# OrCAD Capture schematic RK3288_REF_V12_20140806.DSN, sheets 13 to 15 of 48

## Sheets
13 21.Power-RT5C620_1CELL: size A2; title: Power-RT5C620_1CELL; note: RK808-System Power
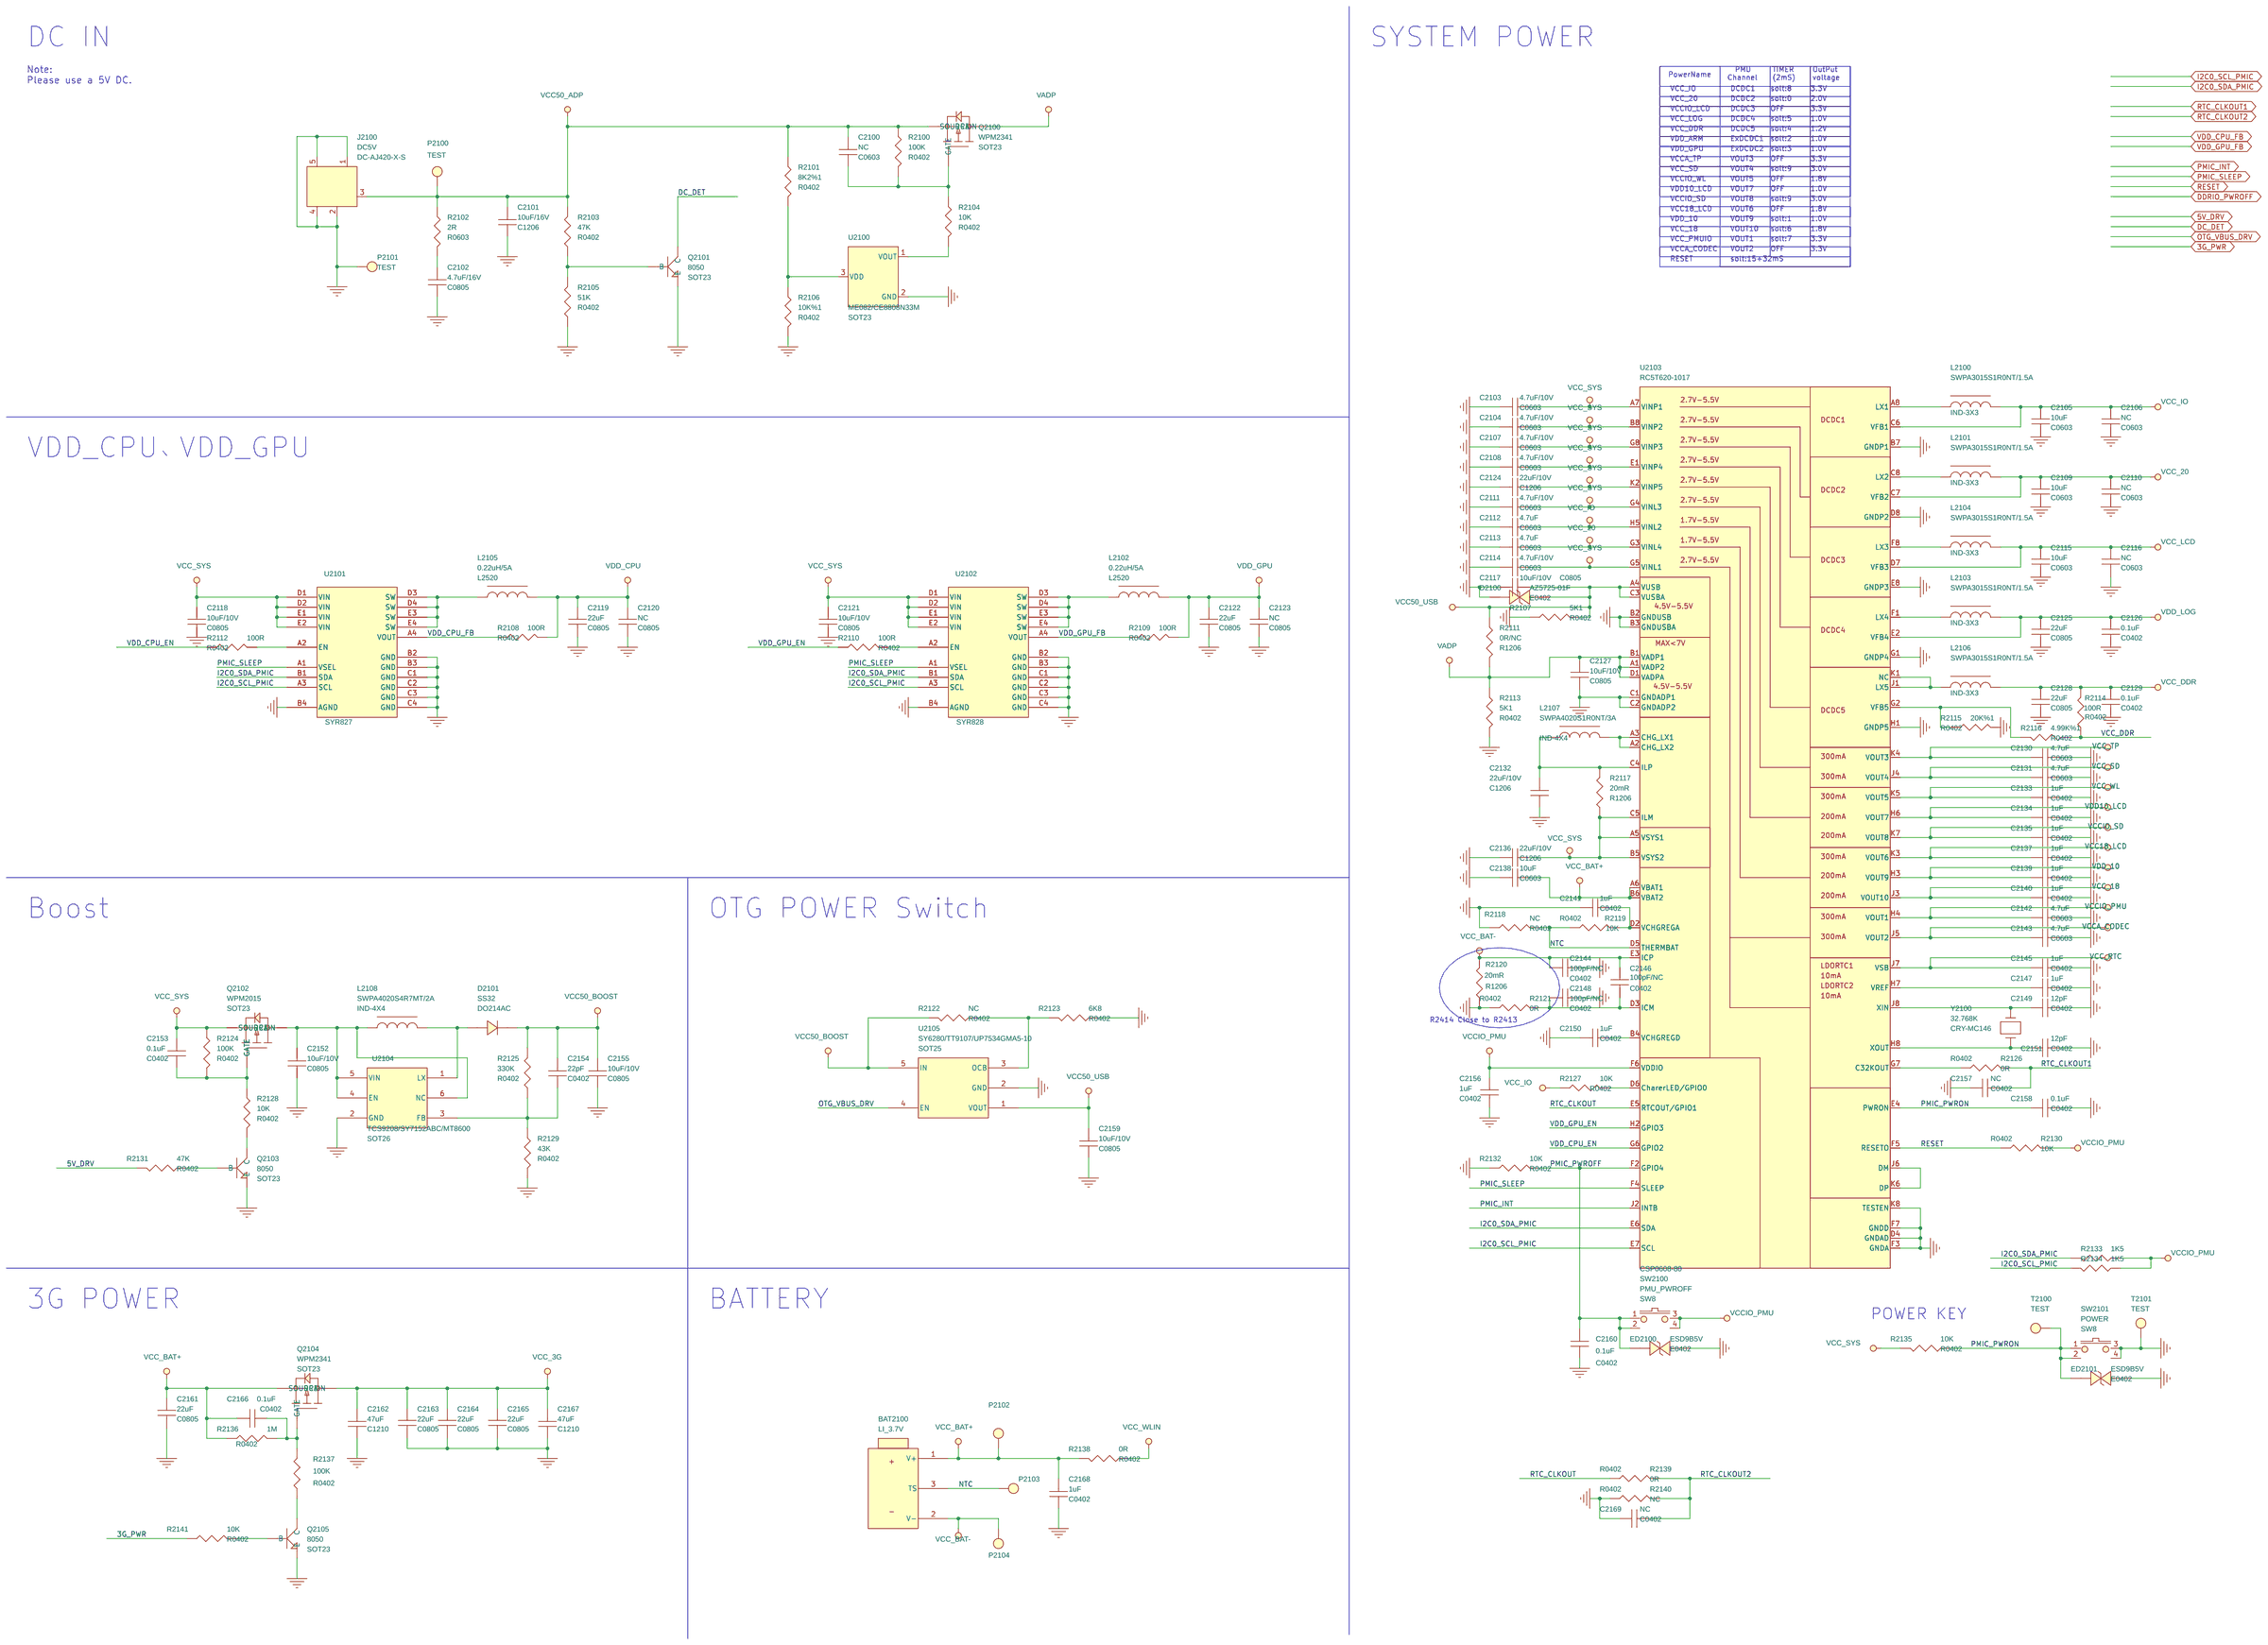
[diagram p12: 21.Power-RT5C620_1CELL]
14 22.Power-ACT8846_2CELL (option): size A2; title: Power-ACT8846_2CELL (option); note: Power Tree
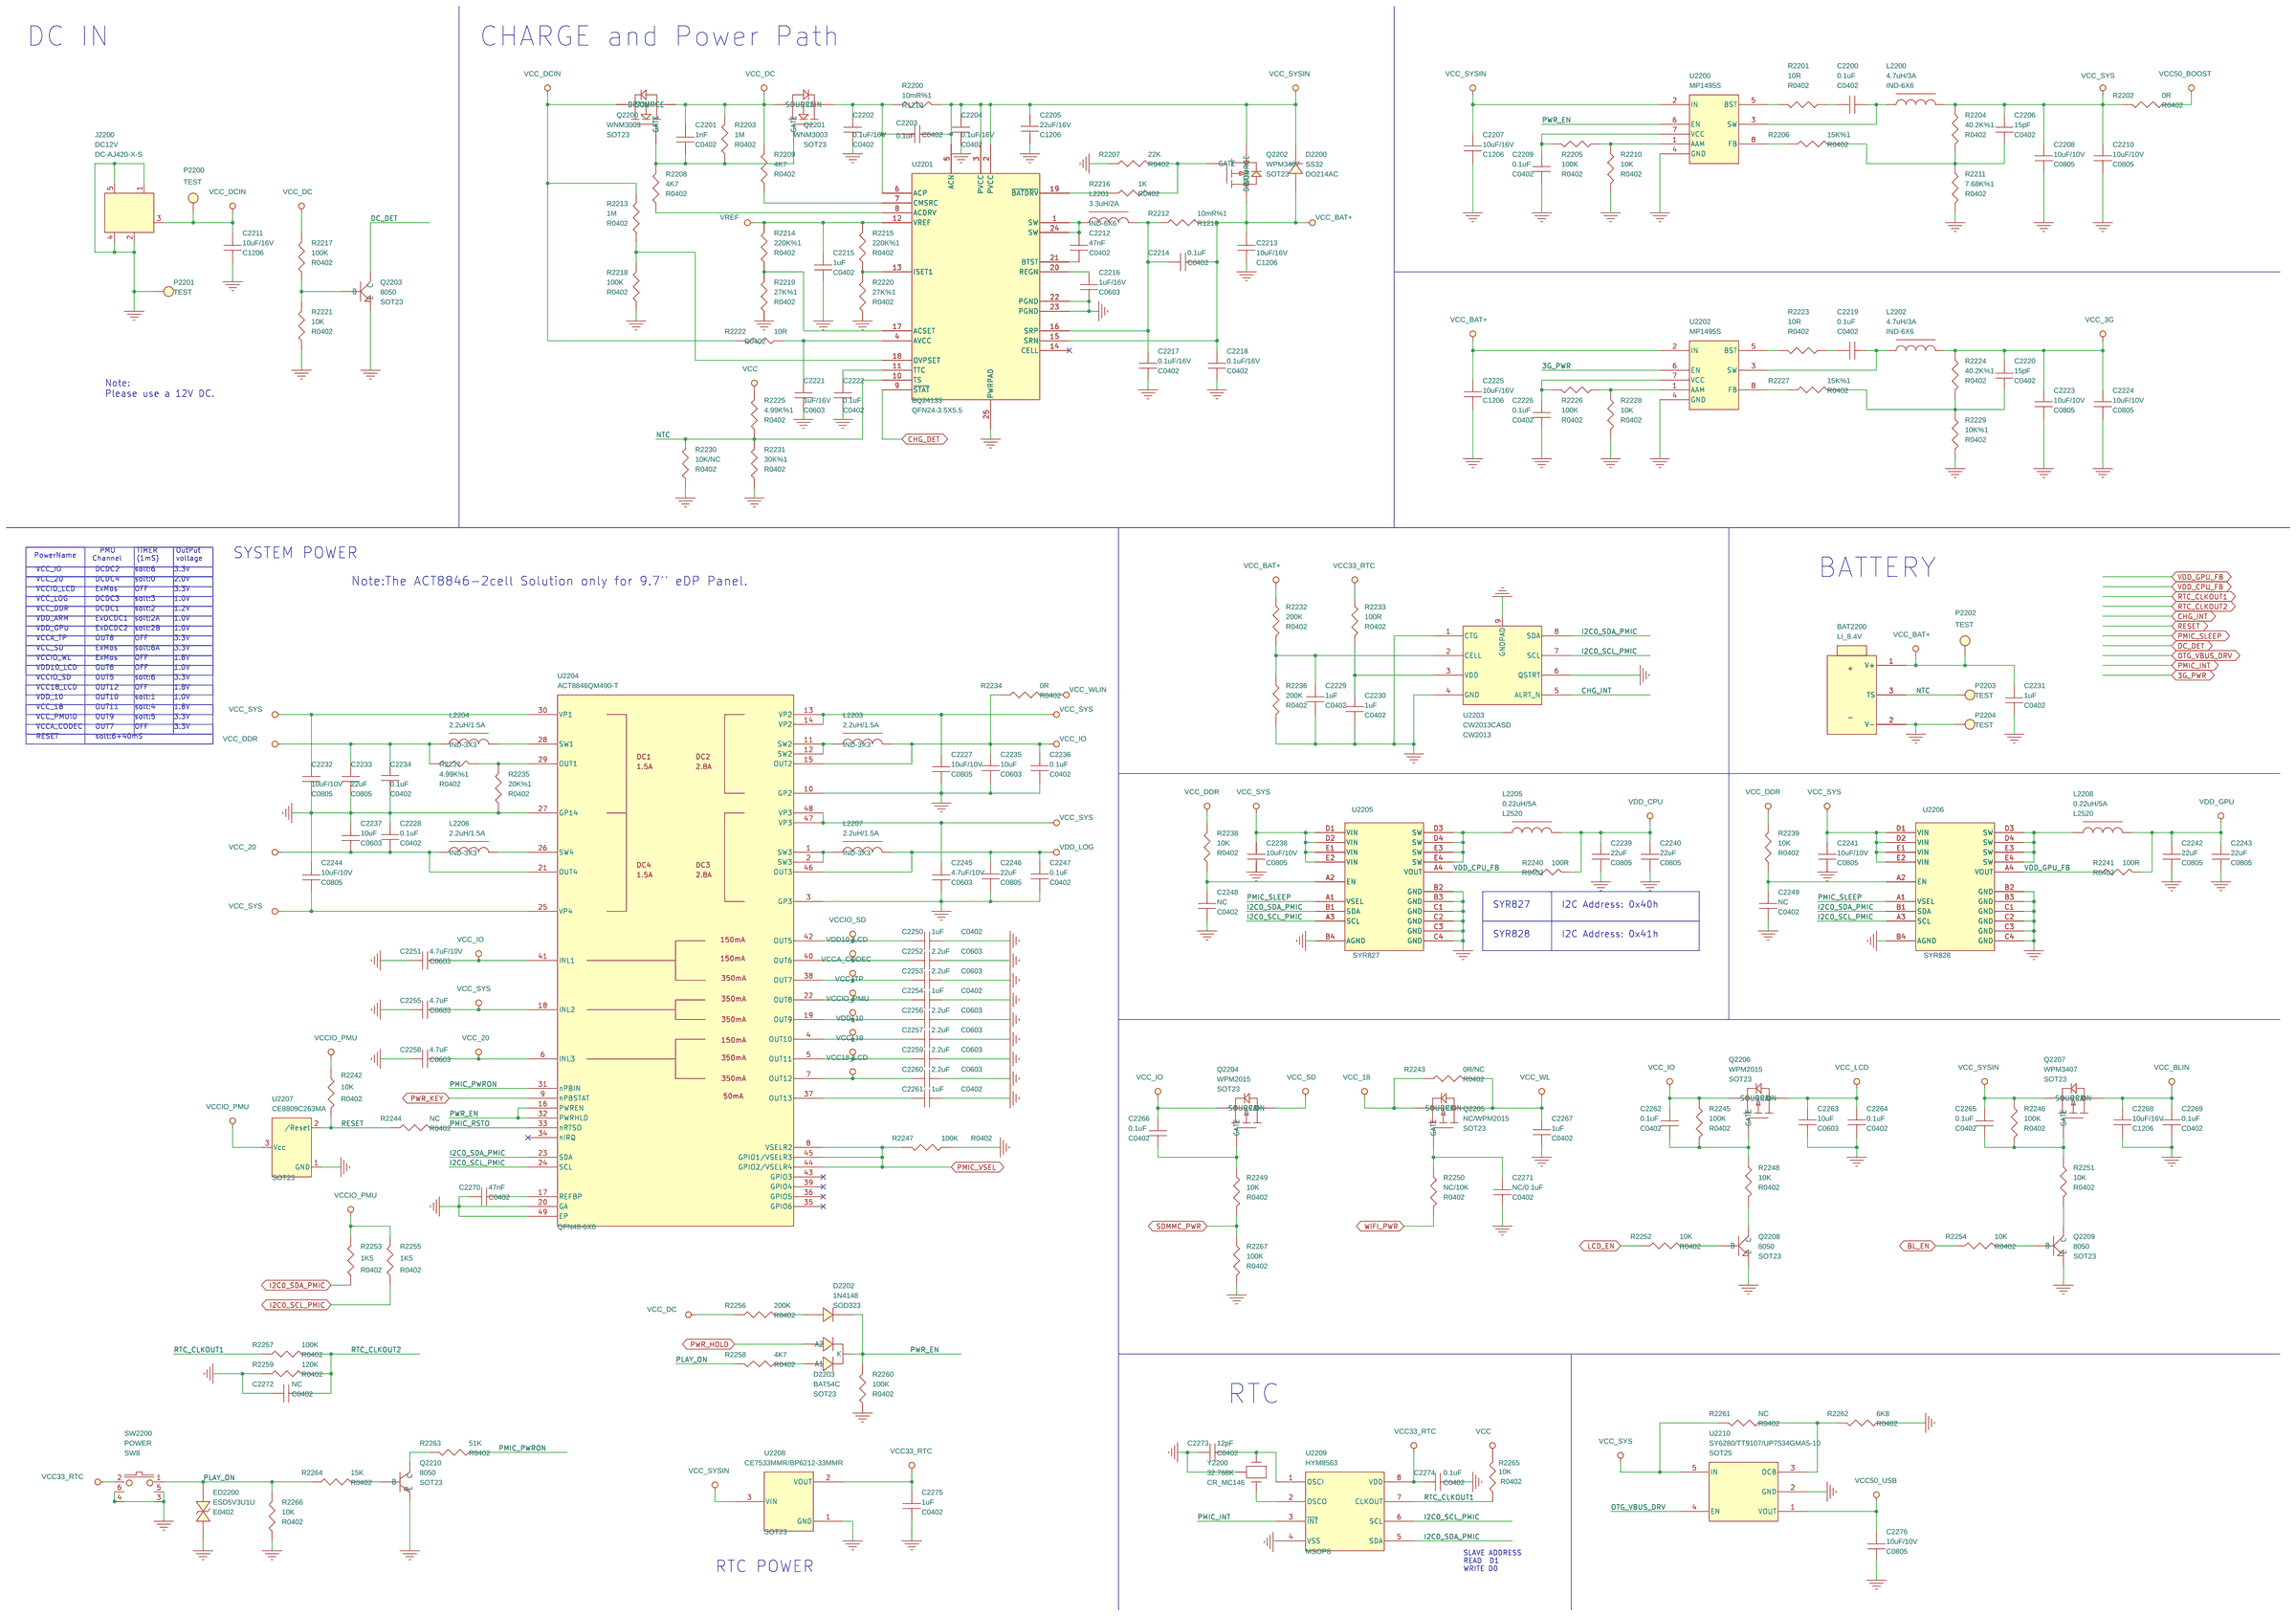
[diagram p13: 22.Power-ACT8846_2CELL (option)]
15 30.RAM-DDR3 4x16bit: size Custom; title: RAM-DDR3 4x16bit; note: RAM-DDR3 4x16bit
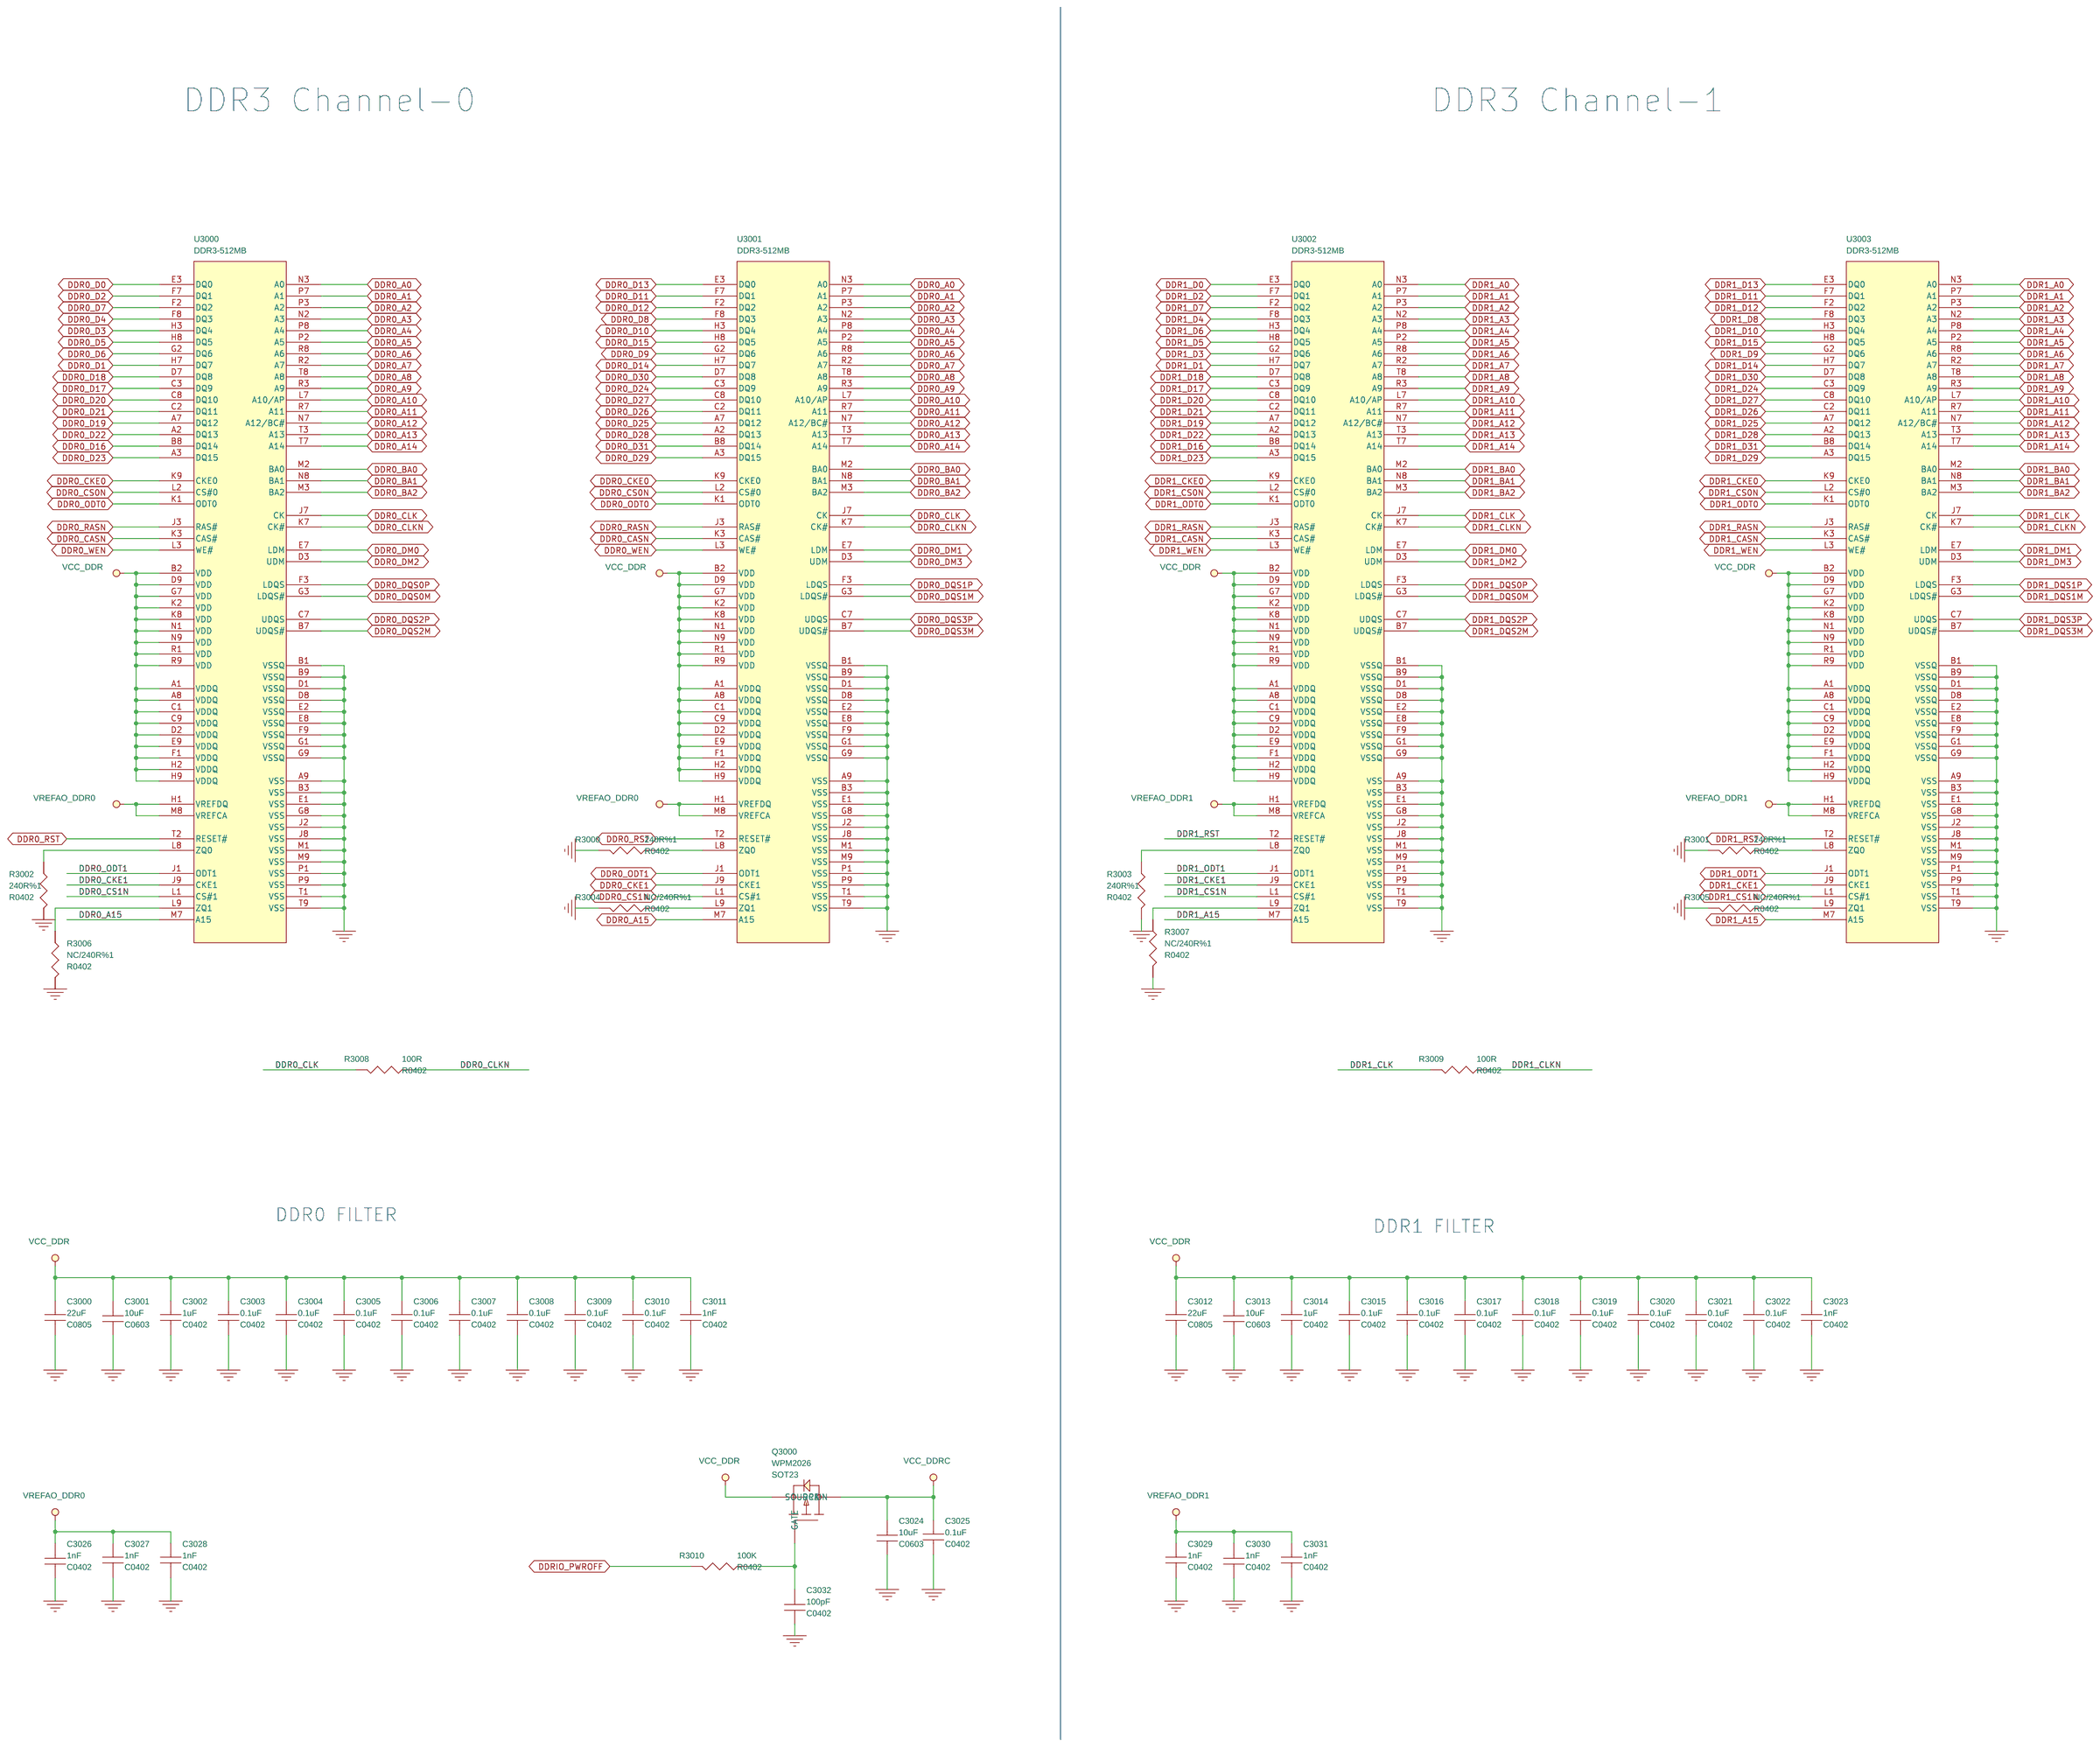
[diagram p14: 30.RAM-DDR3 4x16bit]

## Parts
sheet 21.Power-RT5C620_1CELL
BAT2100  LI_3.7V  [BAT-3]
C2100  NC  [C0603]
C2101  10uF/16V  [C1206]
C2102  4.7uF/16V  [C0805]
C2103  4.7uF/10V  [C0603]
C2104  4.7uF/10V  [C0603]
C2105  10uF  [C0603]
C2106  NC  [C0603]
C2107  4.7uF/10V  [C0603]
C2108  4.7uF/10V  [C0603]
C2109  10uF  [C0603]
C2110  NC  [C0603]
C2111  4.7uF/10V  [C0603]
C2112  4.7uF  [C0603]
C2113  4.7uF  [C0603]
C2114  4.7uF/10V  [C0603]
C2115  10uF  [C0603]
C2116  NC  [C0603]
C2117  10uF/10V  [C0805]
C2118  10uF/10V  [C0805]
C2119  22uF  [C0805]
C2120  NC  [C0805]
C2121  10uF/10V  [C0805]
C2122  22uF  [C0805]
C2123  NC  [C0805]
C2124  22uF/10V  [C1206]
C2125  22uF  [C0805]
C2126  0.1uF  [C0402]
C2127  10uF/10V  [C0805]
C2128  22uF  [C0805]
C2129  0.1uF  [C0402]
C2130  4.7uF  [C0603]
C2131  4.7uF  [C0603]
C2132  22uF/10V  [C1206]
C2133  1uF  [C0402]
C2134  1uF  [C0402]
C2135  1uF  [C0402]
C2136  22uF/10V  [C1206]
C2137  1uF  [C0402]
C2138  10uF  [C0603]
C2139  1uF  [C0402]
C2140  1uF  [C0402]
C2141  1uF  [C0402]
C2142  4.7uF  [C0603]
C2143  4.7uF  [C0603]
C2144  100pF/NC  [C0402]
C2145  1uF  [C0402]
C2146  100pF/NC  [C0402]
C2147  1uF  [C0402]
C2148  100pF/NC  [C0402]
C2149  12pF  [C0402]
C2150  1uF  [C0402]
C2151  12pF  [C0402]
C2152  10uF/10V  [C0805]
C2153  0.1uF  [C0402]
C2154  22pF  [C0402]
C2155  10uF/10V  [C0805]
C2156  1uF  [C0402]
C2157  NC  [C0402]
C2158  0.1uF  [C0402]
C2159  10uF/10V  [C0805]
C2160  0.1uF  [C0402]
C2161  22uF  [C0805]
C2162  47uF  [C1210]
C2163  22uF  [C0805]
C2164  22uF  [C0805]
C2165  22uF  [C0805]
C2166  0.1uF  [C0402]
C2167  47uF  [C1210]
C2168  1uF  [C0402]
C2169  NC  [C0402]
D2100  AZ5725-01F  [E0402]
D2101  SS32  [DO214AC]
ED2100  ESD9B5V  [E0402]
ED2101  ESD9B5V  [E0402]
J2100  DC5V  [DC-AJ420-X-S]
L2100  SWPA3015S1R0NT/1.5A  [IND-3X3]
L2101  SWPA3015S1R0NT/1.5A  [IND-3X3]
L2102  0.22uH/5A  [L2520]
L2103  SWPA3015S1R0NT/1.5A  [IND-3X3]
L2104  SWPA3015S1R0NT/1.5A  [IND-3X3]
L2105  0.22uH/5A  [L2520]
L2106  SWPA3015S1R0NT/1.5A  [IND-3X3]
L2107  SWPA4020S1R0NT/3A  [IND-4X4]
L2108  SWPA4020S4R7MT/2A  [IND-4X4]
P2100  TEST  [T-0.7]
P2101  TEST  [T-0.7]
P2102  TEST  [T-0.7]
P2103  TEST  [T-0.7]
P2104  TEST  [T-0.7]
Q2100  WPM2341  [SOT23]
Q2101  8050  [SOT23]
Q2102  WPM2015  [SOT23]
Q2103  8050  [SOT23]
Q2104  WPM2341  [SOT23]
Q2105  8050  [SOT23]
R2100  100K  [R0402]
R2101  8K2%1  [R0402]
R2102  2R  [R0603]
R2103  47K  [R0402]
R2104  10K  [R0402]
R2105  51K  [R0402]
R2106  10K%1  [R0402]
R2107  5K1  [R0402]
R2108  100R  [R0402]
R2109  100R  [R0402]
R2110  100R  [R0402]
R2111  0R/NC  [R1206]
R2112  100R  [R0402]
R2113  5K1  [R0402]
R2114  100R  [R0402]
R2115  20K%1  [R0402]
R2116  4.99K%1  [R0402]
R2117  20mR  [R1206]
R2118  NC  [R0402]
R2119  10K  [R0402]
R2120  20mR  [R1206]
R2121  0R  [R0402]
R2122  NC  [R0402]
R2123  6K8  [R0402]
R2124  100K  [R0402]
R2125  330K  [R0402]
R2126  0R  [R0402]
R2127  10K  [R0402]
R2128  10K  [R0402]
R2129  43K  [R0402]
R2130  10K  [R0402]
R2131  47K  [R0402]
R2132  10K  [R0402]
R2133  1K5  [R0402]
R2134  1K5  [R0402]
R2135  10K  [R0402]
R2136  1M  [R0402]
R2137  100K  [R0402]
R2138  0R  [R0402]
R2139  0R  [R0402]
R2140  NC  [R0402]
R2141  10K  [R0402]
SW2100  PMU_PWROFF  [SW8]
SW2101  POWER  [SW8]
T2100  TEST  [T-0.7]
T2101  TEST  [T-0.7]
U2100  ME082/CE8808N33M  [SOT23]
U2101  SYR827  [WLCSP-20]
U2102  SYR828  [WLCSP-20]
U2103  RC5T620-1017  [CSP0608-80]
U2104  TCS9208/SY7152ABC/MT8600  [SOT26]
U2105  SY6280/TT9107/UP7534GMA5-10  [SOT25]
Y2100  32.768K  [CRY-MC146]
sheet 22.Power-ACT8846_2CELL (option)
BAT2200  LI_8.4V  [BAT-3]
C2200  0.1uF  [C0402]
C2201  1nF  [C0402]
C2202  0.1uF/16V  [C0402]
C2203  0.1uF  [C0402]
C2204  0.1uF/16V  [C0402]
C2205  22uF/16V  [C1206]
C2206  15pF  [C0402]
C2207  10uF/16V  [C1206]
C2208  10uF/10V  [C0805]
C2209  0.1uF  [C0402]
C2210  10uF/10V  [C0805]
C2211  10uF/16V  [C1206]
C2212  47nF  [C0402]
C2213  10uF/16V  [C1206]
C2214  0.1uF  [C0402]
C2215  1uF  [C0402]
C2216  1uF/16V  [C0603]
C2217  0.1uF/16V  [C0402]
C2218  0.1uF/16V  [C0402]
C2219  0.1uF  [C0402]
C2220  15pF  [C0402]
C2221  1uF/16V  [C0603]
C2222  0.1uF  [C0402]
C2223  10uF/10V  [C0805]
C2224  10uF/10V  [C0805]
C2225  10uF/16V  [C1206]
C2226  0.1uF  [C0402]
C2227  10uF/10V  [C0805]
C2228  0.1uF  [C0402]
C2229  1uF  [C0402]
C2230  1uF  [C0402]
C2231  1uF  [C0402]
C2232  10uF/10V  [C0805]
C2233  22uF  [C0805]
C2234  0.1uF  [C0402]
C2235  10uF  [C0603]
C2236  0.1uF  [C0402]
C2237  10uF  [C0603]
C2238  10uF/10V  [C0805]
C2239  22uF  [C0805]
C2240  22uF  [C0805]
C2241  10uF/10V  [C0805]
C2242  22uF  [C0805]
C2243  22uF  [C0805]
C2244  10uF/10V  [C0805]
C2245  4.7uF/10V  [C0603]
C2246  22uF  [C0805]
C2247  0.1uF  [C0402]
C2248  NC  [C0402]
C2249  NC  [C0402]
C2250  1uF  [C0402]
C2251  4.7uF/10V  [C0603]
C2252  2.2uF  [C0603]
C2253  2.2uF  [C0603]
C2254  1uF  [C0402]
C2255  4.7uF  [C0603]
C2256  2.2uF  [C0603]
C2257  2.2uF  [C0603]
C2258  4.7uF  [C0603]
C2259  2.2uF  [C0603]
C2260  2.2uF  [C0603]
C2261  1uF  [C0402]
C2262  0.1uF  [C0402]
C2263  10uF  [C0603]
C2264  0.1uF  [C0402]
C2265  0.1uF  [C0402]
C2266  0.1uF  [C0402]
C2267  1uF  [C0402]
C2268  10uF/16V  [C1206]
C2269  0.1uF  [C0402]
C2270  47nF  [C0402]
C2271  NC/0.1uF  [C0402]
C2272  NC  [C0402]
C2273  12pF  [C0402]
C2274  0.1uF  [C0402]
C2275  1uF  [C0402]
C2276  10uF/10V  [C0805]
D2200  SS32  [DO214AC]
D2202  1N4148  [SOD323]
D2203  BAT54C  [SOT23]
ED2200  ESD5V3U1U  [E0402]
J2200  DC12V  [DC-AJ420-X-S]
L2200  4.7uH/3A  [IND-6X6]
L2201  3.3uH/2A  [IND-6X6]
L2202  4.7uH/3A  [IND-6X6]
L2203  2.2uH/1.5A  [IND-3X3]
L2204  2.2uH/1.5A  [IND-3X3]
L2205  0.22uH/5A  [L2520]
L2206  2.2uH/1.5A  [IND-3X3]
L2207  2.2uH/1.5A  [IND-3X3]
L2208  0.22uH/5A  [L2520]
P2200  TEST  [T-0.7]
P2201  TEST  [T-0.7]
P2202  TEST  [T-0.7]
P2203  TEST  [T-0.7]
P2204  TEST  [T-0.7]
Q2200  WNM3003  [SOT23]
Q2201  WNM3003  [SOT23]
Q2202  WPM3407  [SOT23]
Q2203  8050  [SOT23]
Q2204  WPM2015  [SOT23]
Q2205  NC/WPM2015  [SOT23]
Q2206  WPM2015  [SOT23]
Q2207  WPM3407  [SOT23]
Q2208  8050  [SOT23]
Q2209  8050  [SOT23]
Q2210  8050  [SOT23]
R2200  10mR%1  [R1210]
R2201  10R  [R0402]
R2202  0R  [R0402]
R2203  1M  [R0402]
R2204  40.2K%1  [R0402]
R2205  100K  [R0402]
R2206  15K%1  [R0402]
R2207  22K  [R0402]
R2208  4K7  [R0402]
R2209  4K7  [R0402]
R2210  10K  [R0402]
R2211  7.68K%1  [R0402]
R2212  10mR%1  [R1210]
R2213  1M  [R0402]
R2214  220K%1  [R0402]
R2215  220K%1  [R0402]
R2216  1K  [R0402]
R2217  100K  [R0402]
R2218  100K  [R0402]
R2219  27K%1  [R0402]
R2220  27K%1  [R0402]
R2221  10K  [R0402]
R2222  10R  [R0402]
R2223  10R  [R0402]
R2224  40.2K%1  [R0402]
R2225  4.99K%1  [R0402]
R2226  100K  [R0402]
R2227  15K%1  [R0402]
R2228  10K  [R0402]
R2229  10K%1  [R0402]
R2230  10K/NC  [R0402]
R2231  30K%1  [R0402]
R2232  200K  [R0402]
R2233  100R  [R0402]
R2234  0R  [R0402]
R2235  20K%1  [R0402]
R2236  200K  [R0402]
R2237  4.99K%1  [R0402]
R2238  10K  [R0402]
R2239  10K  [R0402]
R2240  100R  [R0402]
R2241  100R  [R0402]
R2242  10K  [R0402]
R2243  0R/NC  [R0402]
R2244  NC  [R0402]
R2245  100K  [R0402]
R2246  100K  [R0402]
R2247  100K  [R0402]
R2248  10K  [R0402]
R2249  10K  [R0402]
R2250  NC/10K  [R0402]
R2251  10K  [R0402]
R2252  10K  [R0402]
R2253  1K5  [R0402]
R2254  10K  [R0402]
R2255  1K5  [R0402]
R2256  200K  [R0402]
R2257  100K  [R0402]
R2258  4K7  [R0402]
R2259  120K  [R0402]
R2260  100K  [R0402]
R2261  NC  [R0402]
R2262  6K8  [R0402]
R2263  51K  [R0402]
R2264  15K  [R0402]
R2265  10K  [R0402]
R2266  10K  [R0402]
R2267  100K  [R0402]
SW2200  POWER  [SW8]
U2200  MP1495S  [TSOT_23_8]
U2201  BQ24133  [QFN24-3.5X5.5]
U2202  MP1495S  [TSOT_23_8]
U2203  CW2013CASD  [CW2013]
U2204  ACT8846QM490-T  [QFN48-6X6]
U2205  SYR827  [WLCSP-20]
U2206  SYR828  [WLCSP-20]
U2207  CE8809C263MA  [SOT23]
U2208  CE7533MMR/BP6212-33MMR  [SOT23]
U2209  HYM8563  [MSOP8]
U2210  SY6280/TT9107/UP7534GMA5-10  [SOT25]
Y2200  32.768K  [CR_MC146]
sheet 30.RAM-DDR3 4x16bit
C3000  22uF  [C0805]
C3001  10uF  [C0603]
C3002  1uF  [C0402]
C3003  0.1uF  [C0402]
C3004  0.1uF  [C0402]
C3005  0.1uF  [C0402]
C3006  0.1uF  [C0402]
C3007  0.1uF  [C0402]
C3008  0.1uF  [C0402]
C3009  0.1uF  [C0402]
C3010  0.1uF  [C0402]
C3011  1nF  [C0402]
C3012  22uF  [C0805]
C3013  10uF  [C0603]
C3014  1uF  [C0402]
C3015  0.1uF  [C0402]
C3016  0.1uF  [C0402]
C3017  0.1uF  [C0402]
C3018  0.1uF  [C0402]
C3019  0.1uF  [C0402]
C3020  0.1uF  [C0402]
C3021  0.1uF  [C0402]
C3022  0.1uF  [C0402]
C3023  1nF  [C0402]
C3024  10uF  [C0603]
C3025  0.1uF  [C0402]
C3026  1nF  [C0402]
C3027  1nF  [C0402]
C3028  1nF  [C0402]
C3029  1nF  [C0402]
C3030  1nF  [C0402]
C3031  1nF  [C0402]
C3032  100pF  [C0402]
Q3000  WPM2026  [SOT23]
R3000  240R%1  [R0402]
R3001  240R%1  [R0402]
R3002  240R%1  [R0402]
R3003  240R%1  [R0402]
R3004  NC/240R%1  [R0402]
R3005  NC/240R%1  [R0402]
R3006  NC/240R%1  [R0402]
R3007  NC/240R%1  [R0402]
R3008  100R  [R0402]
R3009  100R  [R0402]
R3010  100K  [R0402]
U3000  DDR3-512MB  [FBGA96-10x14]
U3001  DDR3-512MB  [FBGA96-10x14]
U3002  DDR3-512MB  [FBGA96-10x14]
U3003  DDR3-512MB  [FBGA96-10x14]

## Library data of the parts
BAT2100 BAT2200 = BATTERY_3
C2100 = CAP_NP: RoHS CHIP CAP 4.7uF +10/-10% X7R
C2101 C2211 = CAP_NP: 贴片电容; MARK: 22P; ROOM: USB+5V
C2102 C2159 C2276 = CAP_NP: 贴片电容; MARK: 106; ROOM: USB+5V
C2103-C2117 C2124-C2148 C2150 C2156-C2158 C2160 C2169 C2207 C2208 C2210 C2223-C2225 C2272 = CAP_NP_2: ROOM: CHG
C2118-C2123 C2149 C2151 C2238-C2243 = CAP_NP_4
C2152 C2155 = CAP_NP: RoHS CHIP CAP 10uF +10/-10% X5R; MARK: 106
C2153 C2166 C2236 C2247 C2262 C2265 C2266 C2271 = CAP_NP: RoHS CHIP CAP 0.1uF +10/-10% X7R
C2154 = CAP_NP: RoHS CHIP CAP 22pF 1% NPO
C2161 C2163-C2165 = CAP_NP_4: RoHS CHIP CAP 22uF +10/-10% X5R
C2162 = CAP_NP_2: RoHS CHIP CAP 47uF +10/-10% X5R
C2167 C3000-C3032 = CAP_NP
C2168 C2200 C2206 C2209 C2219 C2220 C2226 C2231 = CAP_NP: RoHS CHIP CAP 1uF +10/-10% 16V X5R
D2100 ED2100 ED2101 ED2200 = DIODE_BI-DIR_TRIG: ESD
D2101 = DIODE: RoHS 1.0A SURFACE MOUNT SCHOTTKY BARRIER RECTIFIER 1N5819
J2100 J2200 = DCJACK_0: DC Jack, 5pin,SMT
L2100-L2108 L2200-L2208 = INDUCTORS_OF_FERRITE
P2100-P2104 P2200-P2204 T2100 T2101 = TESTPOINT1
Q2100 = MOSFET_P: MOSFET-P,WPM2341 ,-20V,+/-8V,-3.2A,56m Ohm@Vgs=-4.5V,69m Ohm@Vgs=-2.5V,86m Ohm@Vgs=-1.8V,SOT23
Q2101 Q2103 Q2105 Q2203 Q2208 Q2209 = NPN4
Q2102 Q2202 Q2204-Q2207 Q3000 = FET_P_MOS
Q2104 = MOSFET_P
R2100 R2104 = RES_1B: ROHS CHIP RES 6.8KOhm 1/16W +/-5%
R2101 = RES_1B: ROHS CHIP RES 6.8K 1/16W 1%
R2102 = RES_1B: RES,thick film,10KOhm,+/-1%,1/16W,SMD0402
R2103 R2105 R2122 R2123 R2217 R2221 R2252 R2254 R2261 R2262 = RESISTOR_0
R2106 = RES_1B: ROHS CHIP RES 10KOhm 1/16W +/-1%
R2107 R2111 R2113-R2121 R2126 R2127 R2130 R2132 R2139 R2140 = RESISTOR_1: 贴片电阻; MARK: 51K; ROOM: USB+5V
R2108-R2110 R2112 R2128 R2131 R2133-R2135 R2238-R2241 R2243 R2248-R2251 R2267 = RESISTOR_1: RES,thick film,47KOhm,+/-5%,1/16W,SMD0402
R2124 R2245 R2246 = RES_1B: ROHS CHIP RES 100K 1/16W 1%
R2125 = RESISTOR_0: ROHS CHIP RES 330K 1/16W +/-5%; MARK: 51K
R2129 = RESISTOR_0: ROHS CHIP RES 43K 1/16W +/-5%; MARK: 51K
R2136 = RESISTOR_3: ROHS CHIP RES 100K 1/16W +/-5%
R2137 = RESISTOR_3: ROHS CHIP RES 10K 1/16W +/-5%
R2138 R2201 R2202 R2204-R2206 R2210 R2211 R2223 R2224 R2226-R2229 = RESISTOR_0: RES,thick film,47KOhm,+/-5%,1/16W,SMD0402; MARK: 51K
R2141 = RESISTOR_3: ROHS CHIP RES 22K 1/16W +/-5%
SW2100 SW2101 = SW4P_0: 按键
U2100 = BL8506: Voltage Detectors,VDD=0.7V~5V,Vrst=3.3 V ±2.0 %, SOT 23  ,-40°C~+ 85°
U2101 U2102 U2205 U2206 = BB27_0
U2103 = 5T619_2
U2104 = G5121_1: SY7208/TCS9208/LP6218 High Efficiency 1MHz, 2A Step Up Regulator
U2105 U2210 = DS8008_3: 开关IC; MARK: RT9701/G5250
Y2100 = CRYSTAL: Crystal,32.768KHz,+/-30ppm,12pF,MC146,-10°C ~ +60   °C; Part Type: 晶体类\无源晶体
C2201 C2215 C2248 C2249 = CAP_NP: RoHS CHIP CAP 1uF +10/-10% X5R; MARK: 22P; ROOM: USB+5V
C2202 C2204 C2217 C2218 = CAP_NP: RoHS CHIP CAP 0.1uF +10/-10% 16V X7R; MARK: 22P; ROOM: USB+5V
C2203 C2214 C2222 = CAP_NP: RoHS CHIP CAP 0.1uF +10/-10% X7R; MARK: 22P; ROOM: USB+5V
C2205 = CAP_NP: RoHS CHIP CAP 22uF +80/-20% 16V Y5V; ROOM: CHG
C2212 = CAP_NP: RoHS CHIP CAP 47nF +10/-10% X7R; MARK: 22P; ROOM: USB+5V
C2213 = CAP_NP: RoHS CHIP CAP 10uF +10/-10% 16V X5R; MARK: 106; ROOM: USB+5V
C2216 C2221 = CAP_NP: RoHS CHIP CAP 1uF +10/-10% 16V X5R; MARK: 22P; ROOM: USB+5V
C2227 C2232 C2233 C2237 C2244 C2245 = CAP_NP: RoHS CHIP CAP 10uF ±10% X7R; MARK: 106; ROOM: USB+5V
C2228 C2234 C2250 C2252-C2254 C2256 C2257 C2259 C2260 = CAP_NP: RoHS CHIP CAP 2.2uF +10/-10% X5R; ROOM: CHG
C2229 C2275 = CAP_NP: RoHS CHIP CAP 1uF +10/-10% X5R
C2230 = CAP_NP: RoHS CHIP CAP 10nF +10/-10% X7R
C2235 C2246 = CAP_NP: RoHS CHIP CAP 22uF +10/-10% X5R; MARK: 106; ROOM: USB+5V
C2251 C2255 C2258 = CAP_NP: RoHS CHIP CAP 4.7uF +10/-10% X5R; ROOM: CHG
C2261 = CAP_NP: RoHS CHIP CAP 1uF +10/-10% X5R; ROOM: CHG
C2263 C2268 = CAP_NP: CAP,MLCC,4.7uF,+/-10%,X5R,6.3V,SMD0603
C2264 C2267 C2269 = CAP_NP: CAP,MLCC,100nF,+/-10%,X7R,6.3V,SMD0402
C2270 = CAP_NP: RoHS CHIP CAP 47nF +10/-10% X5R
C2273 = CAP_NP: CAP,MLCC,12pF,+/-10%,NPO,6.3V,SMD0402
C2274 = CAP_NP: CAP,MLCC,1uF,+/-10%,X5R,6.3V,SMD0402
D2200 = DIODE: Diode,Schottky,SS32,20V,3A,750mV,DO-214AC; ROOM: CHG
D2202 = DIODE: Diode,Schottky,1N4148,40V,100mA,600mV,SOD-323; ROOM: CHG
D2203 = BAT54C: Schottky barrier(double) diodes,30V,200mA,SOT23,-40°C~ +125 °C
Q2200 Q2201 = MOSFET_N: MOSFET-N,WNM3003 ,30V,+/-20V,4.0A,33m Ohm@Vgs=10V,43m Ohm@Vgs=4.5V,SOT23
Q2210 = NPN
R2200 R2212 = RESISTOR: ROHS CHIP RES 10mOhm 1/3W 1%; MARK: 2K; ROOM: USB+5V
R2203 R2214 R2215 R2258 = RESISTOR: ROHS CHIP RES 220K 1/16W 5%; MARK: 2K; ROOM: USB+5V
R2207 = RESISTOR: ROHS CHIP RES 22K 1/16W 5%
R2208 R2209 = RESISTOR: ROHS CHIP RES 4.7K 1/16W 5%; MARK: 2K; ROOM: USB+5V
R2213 = RESISTOR: ROHS CHIP RES 1M 1/16W 5%; MARK: 2K; ROOM: USB+5V
R2216 = RESISTOR: ROHS CHIP RES 1K 1/16W 5%
R2218 = RESISTOR: ROHS CHIP RES 100K 1/16W 5%; MARK: 2K; ROOM: USB+5V
R2219 = RESISTOR: ROHS CHIP RES 30K 1/16W 5%; MARK: 2K; ROOM: USB+5V
R2220 = RESISTOR: ROHS CHIP RES 27K 1/16W 5%; MARK: 2K; ROOM: USB+5V
R2222 = RESISTOR: ROHS CHIP RES 10R 1/16W 5%
R2225 = RESISTOR: ROHS CHIP RES 4.99K 1/16W 1%; MARK: 2K; ROOM: USB+5V
R2230 R2231 = RESISTOR: ROHS CHIP RES 30K 1/16W 1%; MARK: 2K; ROOM: USB+5V
R2232 R2234 R2236 = RESISTOR: ROHS CHIP RES 1K 1/16W +/-5%
R2233 = RESISTOR: ROHS CHIP RES  150R 1/16W +/-5%
R2235 = RESISTOR_1: ROHS CHIP RES 20K 1/16W ±1%; MARK: 51K; ROOM: USB+5V
R2237 = RESISTOR_1: ROHS CHIP RES 4.99K 1/16W ±1%; MARK: 51K; ROOM: USB+5V
R2242 R2244 R2253 R2255 = RESISTOR_1: ROHS CHIP RES 10K 1/16W ±5电阻; MARK: 51K; ROOM: USB+5V
R2247 = RESISTOR_0: ROHS CHIP RES 47K 1/16W 5%
R2256 = RESISTOR: ROHS CHIP RES 220K 1/16W 5%
R2257 R2259 R2265 = RESISTOR_4: RES,thick film,10KOhm,+/-5%,1/16W,SMD0402
R2260 = RESISTOR: ROHS CHIP RES 100K 1/16W 5%
R2263 R2264 R2266 = RESISTOR_1
SW2200 = SW4P_3: KEY,SMT
U2200 U2202 = BUCK-MP1495
U2201 = BQ24133: Charger IC witch power switch,1.6MHz,2A,4.5V~16.5V,QFN24,-40°C~ +85  °C
U2203 = Gage-CW2013: Fuel Gauge with Low-SOC Alert,2.5V~4.5V,TDFN8,-20 ~70℃
U2204 = PMIC_ACT8846: PMU IC
U2207 = RESET
U2208 = CE71XXMM: High voltage LDO,CE7521MMR,50mA,2.1V output,-0.3V~18V input,SOT23,-40°C~ +85  °C
U2209 = RTC: RTC IC,CMOS RTC/Calendar,1.0V~5.5V,TSSOP8,-40 ~85℃
Y2200 = CRYSTAL-4P
R3000-R3009 = RESISTOR_0: 贴片电阻
R3010 = RESISTOR_0: RES,thick film,1MOhm,+/-5%,1/16W,SMD0402; MARK: 51K
U3000-U3003 = DDR3_FBGA96

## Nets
5V_DRV: R2131.1 ; also on sheet 11
GND: BAT2200.2(V-) C2101.1 C2102.1 C2103.2 C2104.2 C2105.2 C2106.2 C2107.2 C2108.2 C2109.2 C2110.2 C2111.2 C2112.2 C2113.2 C2114.2 C2115.2 C2116.2 C2117.2 C2118.2 C2119.2 C2120.2 C2121.2 C2122.2 C2123.2 C2124.2 C2125.2 C2126.2 C2127.2 C2128.2 C2129.2 C2130.2 C2131.2 C2132.1 C2133.2 C2134.2 C2135.2 C2136.2 C2137.2 C2138.2 C2139.2 C2140.2 C2141.2 C2142.2 C2143.2 C2144.1 C2145.2 C2147.2 C2148.1 C2149.2 C2150.2 C2151.2 C2152.1 C2155.1 C2156.2 C2157.1 C2158.2 C2159.1 C2160.1 C2161.2 C2162.1 C2163.2 C2164.2 C2165.2 C2167.1 C2168.1 C2169.1 C2202.1 C2204.1 C2205.2 C2207.2 C2208.2 C2209.1 C2210.2 C2211.1 C2213.1 C2215.1 C2216.1 C2217.1 C2218.1 C2221.1 C2222.1 C2223.2 C2224.2 C2225.2 C2226.1 C2227.1 C2228.1 C2229.2 C2230.2 C2231.1 C2232.1 C2233.1 C2234.2 C2235.2 C2236.2 C2237.2 C2238.2 C2239.2 C2240.2 C2241.2 C2242.2 C2243.2 C2244.2 C2245.1 C2246.2 C2247.2 C2248.2 C2249.2 C2250.1 C2251.2 C2252.1 C2253.1 C2254.1 C2255.2 C2256.1 C2257.1 C2258.2 C2259.1 C2260.1 C2261.1 C2263.2 C2264.2 C2267.2 C2268.2 C2269.2 C2270.2 C2271.1 C2272.1 C2273.2 C2274.2 C2275.2 C2276.1 C3000.2 C3001.1 C3002.2 C3003.2 C3004.2 C3005.2 C3006.2 C3007.2 C3008.2 C3009.2 C3010.2 C3011.2 C3012.2 C3013.1 C3014.2 C3015.2 C3016.2 C3017.2 C3018.2 C3019.2 C3020.2 C3021.2 C3022.2 C3023.2 C3024.1 C3025.2 C3026.1 C3027.2 C3028.2 C3029.2 C3030.1 C3031.2 C3032.1 D2100.1 ED2100.2 ED2101.2 ED2200.2 J2100.1 J2100.2 J2100.4 J2100.5 J2200.1 J2200.2 J2200.4 J2200.5 P2101.1 P2201.1 P2204.1 Q2101.2(E) Q2103.2(E) Q2105.2(E) Q2203.2(E) Q2208.2(E) Q2209.2(E) Q2210.2(E) R2105.1 R2106.2 R2107.1 R2113.2 R2115.2 R2118.2 R2120.1 R2121.2 R2123.1 R2129.2 R2132.1 R2140.2 R2207.1 R2210.2 R2211.2 R2218.1 R2219.1 R2220.1 R2221.1 R2228.2 R2229.2 R2230.1 R2231.1 R2235.1 R2236.1 R2247.1 R2259.1 R2260.2 R2262.1 R2266.2 R2267.1 R3000.2 R3001.2 R3002.2 R3003.2 R3004.2 R3005.2 R3006.2 R3007.2 SW2101.3 SW2101.4 SW2200.3 SW2200.4 SW2200.5 SW2200.6 T2101.1 U2100.2(GND) U2101.B2(GND) U2101.B3(GND) U2101.B4(AGND) U2101.C1(GND) U2101.C2(GND) U2101.C3(GND) U2101.C4(GND) U2102.B2(GND) U2102.B3(GND) U2102.B4(AGND) U2102.C1(GND) U2102.C2(GND) U2102.C3(GND) U2102.C4(GND) U2103.B2(GNDUSB) U2103.B3(GNDUSBA) U2103.B7(GNDP1) U2103.C1(GNDADP1) U2103.C2(GNDADP2) U2103.D4(GNDAD) U2103.D8(GNDP2) U2103.E8(GNDP3) U2103.F3(GNDA) U2103.F7(GNDD) U2103.G1(GNDP4) U2103.H1(GNDP5) U2103.K8(TESTEN) U2104.2(GND) U2105.2(GND) U2200.4(GND) U2201.22(PGND) U2201.23(PGND) U2201.25(PWRPAD) U2202.4(GND) U2203.1(CTG) U2203.4(GND) U2203.6(QSTRT) U2203.9(GNDPAD) U2204.3(GP3) U2204.10(GP2) U2204.20(GA) U2204.27(GP14) U2204.49(EP) U2205.B2(GND) U2205.B3(GND) U2205.B4(AGND) U2205.C1(GND) U2205.C2(GND) U2205.C3(GND) U2205.C4(GND) U2206.B2(GND) U2206.B3(GND) U2206.B4(AGND) U2206.C1(GND) U2206.C2(GND) U2206.C3(GND) U2206.C4(GND) U2207.1(GND) U2208.1(GND) U2209.4(VSS) U2210.2(GND) U3000.A9(VSS) U3000.B1(VSSQ) U3000.B3(VSS) U3000.B9(VSSQ) U3000.D1(VSSQ) U3000.D8(VSSQ) U3000.E1(VSS) U3000.E2(VSSQ) U3000.E8(VSSQ) U3000.F9(VSSQ) U3000.G1(VSSQ) U3000.G8(VSS) U3000.G9(VSSQ) U3000.J2(VSS) U3000.J8(VSS) U3000.M1(VSS) U3000.M9(VSS) U3000.P1(VSS) U3000.P9(VSS) U3000.T1(VSS) U3000.T9(VSS) U3001.A9(VSS) U3001.B1(VSSQ) U3001.B3(VSS) U3001.B9(VSSQ) U3001.D1(VSSQ) U3001.D8(VSSQ) U3001.E1(VSS) U3001.E2(VSSQ) U3001.E8(VSSQ) U3001.F9(VSSQ) U3001.G1(VSSQ) U3001.G8(VSS) U3001.G9(VSSQ) U3001.J2(VSS) U3001.J8(VSS) U3001.M1(VSS) U3001.M9(VSS) U3001.P1(VSS) U3001.P9(VSS) U3001.T1(VSS) U3001.T9(VSS) U3002.A9(VSS) U3002.B1(VSSQ) U3002.B3(VSS) U3002.B9(VSSQ) U3002.D1(VSSQ) U3002.D8(VSSQ) U3002.E1(VSS) U3002.E2(VSSQ) U3002.E8(VSSQ) U3002.F9(VSSQ) U3002.G1(VSSQ) U3002.G8(VSS) U3002.G9(VSSQ) U3002.J2(VSS) U3002.J8(VSS) U3002.M1(VSS) U3002.M9(VSS) U3002.P1(VSS) U3002.P9(VSS) U3002.T1(VSS) U3002.T9(VSS) U3003.A9(VSS) U3003.B1(VSSQ) U3003.B3(VSS) U3003.B9(VSSQ) U3003.D1(VSSQ) U3003.D8(VSSQ) U3003.E1(VSS) U3003.E2(VSSQ) U3003.E8(VSSQ) U3003.F9(VSSQ) U3003.G1(VSSQ) U3003.G8(VSS) U3003.G9(VSSQ) U3003.J2(VSS) U3003.J8(VSS) U3003.M1(VSS) U3003.M9(VSS) U3003.P1(VSS) U3003.P9(VSS) U3003.T1(VSS) U3003.T9(VSS) Y2200.3 Y2200.4 ; also on sheet 5 6 7 8 9 10 11 12 16 17 18 19 20 21 22 23 24 25 26 27 28 29 30 31 32 33 34 35 36 37 38 39 40 41 42 43 44 45 46 47 48
VCC18_LCD: C2137.1 C2260.2 U2103.K3(VOUT6) U2204.7(OUT12) ; also on sheet 10 29
VCC33_RTC: C2274.1 C2275.1 R2233.2 SW2200.2 U2208.2(VOUT) U2209.8(VDD)
VCC50_ADP: C2100.2 C2101.2 J2100.3 P2100.1 Q2100.2(SOURCE) R2100.1 R2101.1 R2102.1 R2103.2
VCC50_BOOST: C2154.2 C2155.2 D2101.2(K) R2122.2 R2125.1 R2202.1 U2105.5(IN) ; also on sheet 41
VCC50_USB: C2117.1 C2159.2 C2276.2 D2100.2 R2107.2 R2111.1 U2103.A4(VUSB) U2103.C3(VUSBA) U2105.1(VOUT) U2210.1(VOUT) ; also on sheet 12
VCC_3G: C2162.2 C2163.1 C2164.1 C2165.1 C2167.2 C2220.2 C2223.1 C2224.1 L2202.2 Q2104.3(DRAIN) R2224.1 ; also on sheet 31 32
VCC_18: C2140.1 C2259.2 Q2205.2(SOURCE) R2243.2 U2103.J3(VOUT10) U2204.5(OUT11) ; also on sheet 17 18 19 20 32 33 34 35 45 46
VCC_20: C2109.1 C2110.1 C2113.1 C2228.2 C2237.1 C2258.1 L2101.2 L2206.1 U2103.C7(VFB2) U2103.G3(VINL4) U2204.6(INL3) U2204.21(OUT4) ; also on sheet 24
VCC_BAT+: BAT2100.1(V+) BAT2200.1(V+) C2138.1 C2161.1 C2166.2 C2168.2 C2213.2 C2214.1 C2218.2 C2225.1 C2231.2 D2200.1(A) P2102.1 P2202.1 Q2104.2(SOURCE) Q2202.3(DRAIN) R2136.2 R2138.2 R2212.2 R2232.2 U2103.A6(VBAT1) U2103.B6(VBAT2) U2201.15(SRN) U2202.2(IN)
VCC_BAT-: BAT2100.2(V-) C2144.2 C2146.1 P2104.1 R2120.2 U2103.E3(ICP)
VCC_BLIN: C2268.1 C2269.1 Q2207.3(DRAIN) ; also on sheet 27
VCC_DC: C2201.2 Q2200.2(SOURCE) Q2201.2(SOURCE) R2203.2 R2209.2 R2217.2 R2256.2
VCC_DCIN: C2211.2 J2200.3 P2200.1 Q2200.3(DRAIN) R2213.2 R2222.2
VCC_DDR: C2128.1 C2129.1 C2233.2 C2234.1 C3000.1 C3001.2 C3002.1 C3003.1 C3004.1 C3005.1 C3006.1 C3007.1 C3008.1 C3009.1 C3010.1 C3011.1 C3012.1 C3013.2 C3014.1 C3015.1 C3016.1 C3017.1 C3018.1 C3019.1 C3020.1 C3021.1 C3022.1 C3023.1 L2106.2 L2204.1 Q3000.2(SOURCE) R2114.1 R2114.2 R2116.1 R2237.1 R2238.1 R2239.1 U3000.A1(VDDQ) U3000.A8(VDDQ) U3000.B2(VDD) U3000.C1(VDDQ) U3000.C9(VDDQ) U3000.D2(VDDQ) U3000.D9(VDD) U3000.E9(VDDQ) U3000.F1(VDDQ) U3000.G7(VDD) U3000.H2(VDDQ) U3000.H9(VDDQ) U3000.K2(VDD) U3000.K8(VDD) U3000.N1(VDD) U3000.N9(VDD) U3000.R1(VDD) U3000.R9(VDD) U3001.A1(VDDQ) U3001.A8(VDDQ) U3001.B2(VDD) U3001.C1(VDDQ) U3001.C9(VDDQ) U3001.D2(VDDQ) U3001.D9(VDD) U3001.E9(VDDQ) U3001.F1(VDDQ) U3001.G7(VDD) U3001.H2(VDDQ) U3001.H9(VDDQ) U3001.K2(VDD) U3001.K8(VDD) U3001.N1(VDD) U3001.N9(VDD) U3001.R1(VDD) U3001.R9(VDD) U3002.A1(VDDQ) U3002.A8(VDDQ) U3002.B2(VDD) U3002.C1(VDDQ) U3002.C9(VDDQ) U3002.D2(VDDQ) U3002.D9(VDD) U3002.E9(VDDQ) U3002.F1(VDDQ) U3002.G7(VDD) U3002.H2(VDDQ) U3002.H9(VDDQ) U3002.K2(VDD) U3002.K8(VDD) U3002.N1(VDD) U3002.N9(VDD) U3002.R1(VDD) U3002.R9(VDD) U3003.A1(VDDQ) U3003.A8(VDDQ) U3003.B2(VDD) U3003.C1(VDDQ) U3003.C9(VDDQ) U3003.D2(VDDQ) U3003.D9(VDD) U3003.E9(VDDQ) U3003.F1(VDDQ) U3003.G7(VDD) U3003.H2(VDDQ) U3003.H9(VDDQ) U3003.K2(VDD) U3003.K8(VDD) U3003.N1(VDD) U3003.N9(VDD) U3003.R1(VDD) U3003.R9(VDD) ; also on sheet 7 16 17 18 19 20
VCC_DDRC: C3024.2 C3025.1 Q3000.3(DRAIN) ; also on sheet 7 16 17 18 19 20
VCC_IO: C2105.1 C2106.1 C2112.1 C2235.1 C2236.1 C2251.1 C2262.2 C2266.2 L2100.2 L2203.2 Q2204.2(SOURCE) Q2206.2(SOURCE) R2127.2 R2234.2 R2245.2 U2103.C6(VFB1) U2103.H5(VINL2) U2204.15(OUT2) U2204.41(INL1) ; also on sheet 11 21 22 23 24 31 32 33 34 35 41 42 43
VCC_LCD: C2115.1 C2116.1 C2263.1 C2264.1 L2104.2 Q2206.3(DRAIN) U2103.D7(VFB3) ; also on sheet 5 10 27 28 29 30
VCC_RTC: C2145.1 U2103.J7(VSB)
VCC_SD: C2131.1 Q2204.3(DRAIN) U2103.J4(VOUT4) ; also on sheet 40
VCC_SYS: C2103.1 C2104.1 C2107.1 C2108.1 C2111.1 C2114.1 C2118.1 C2121.1 C2124.1 C2136.1 C2153.2 C2206.2 C2208.1 C2210.1 C2227.2 C2232.2 C2238.1 C2241.1 C2244.1 C2245.2 C2255.1 L2200.2 Q2102.2(SOURCE) R2117.1 R2124.2 R2135.2 R2202.2 R2204.1 R2261.2 U2101.D1(VIN) U2101.D2(VIN) U2101.E1(VIN) U2101.E2(VIN) U2102.D1(VIN) U2102.D2(VIN) U2102.E1(VIN) U2102.E2(VIN) U2103.A5(VSYS1) U2103.A7(VINP1) U2103.B5(VSYS2) U2103.B8(VINP2) U2103.C5(ILM) U2103.E1(VINP4) U2103.G4(VINL3) U2103.G5(VINL1) U2103.G8(VINP3) U2103.K2(VINP5) U2204.13(VP2) U2204.14(VP2) U2204.18(INL2) U2204.25(VP4) U2204.30(VP1) U2204.47(VP3) U2204.48(VP3) U2205.D1(VIN) U2205.D2(VIN) U2205.E1(VIN) U2205.E2(VIN) U2206.D1(VIN) U2206.D2(VIN) U2206.E1(VIN) U2206.E2(VIN) U2210.5(IN) ; also on sheet 24 27 28 29 30 33 34 35 43
VCC_SYSIN: C2203.1 C2204.2 C2205.1 C2207.1 C2265.2 D2200.2(K) Q2202.2(SOURCE) Q2207.2(SOURCE) R2200.2 R2246.2 U2200.2(IN) U2201.2(PVCC) U2201.3(PVCC) U2201.5(ACN) U2208.3(VIN)
VCC_TP: C2130.1 C2254.2 U2103.K4(VOUT3) U2204.22(OUT8) ; also on sheet 36 37 38 39 43
VCC_WL: C2133.1 C2267.1 Q2205.3(DRAIN) R2243.1 U2103.K5(VOUT5) ; also on sheet 11 44 47 48
VCC_WLIN: R2138.1 R2234.1 ; also on sheet 44 47 48
VCCA_CODEC: C2143.1 C2253.2 U2103.J5(VOUT2) U2204.38(OUT7) ; also on sheet 31 32 33 34 35
VCCIO_PMU: C2142.1 C2156.1 C2256.2 R2130.1 R2133.2 R2134.2 R2242.1 R2253.2 R2255.2 R2265.2 SW2100.3 SW2100.4 U2103.F6(VDDIO) U2103.H4(VOUT1) U2204.19(OUT9) U2207.3(Vcc) ; also on sheet 6 11 17 18 19 20 24 33 34 35 41 43 46
VCCIO_SD: C2135.1 C2250.2 U2103.K7(VOUT8) U2204.42(OUT5) ; also on sheet 11 40
VDD10_LCD: C2134.1 C2252.2 U2103.H6(VOUT7) U2204.40(OUT6) ; also on sheet 10
VDD_10: C2139.1 C2257.2 U2103.H3(VOUT9) U2204.4(OUT10) ; also on sheet 6 46
VDD_CPU: C2119.1 C2120.1 C2239.1 C2240.1 L2105.2 L2205.2 R2108.1 R2240.1 ; also on sheet 5
VDD_CPU_EN: R2112.2 U2103.G6(GPIO2)
VDD_CPU_FB: R2108.2 R2240.2 U2101.A4(VOUT) U2205.A4(VOUT) ; also on sheet 5
VDD_GPU: C2122.1 C2123.1 C2242.1 C2243.1 L2102.2 L2208.2 R2109.1 R2241.1 ; also on sheet 5
VDD_GPU_EN: R2110.2 U2103.H2(GPIO3)
VDD_GPU_FB: R2109.2 R2241.2 U2102.A4(VOUT) U2206.A4(VOUT) ; also on sheet 5
VDD_LOG: C2125.1 C2126.1 C2246.1 C2247.1 L2103.2 L2207.2 U2103.E2(VFB4) U2204.46(OUT3) ; also on sheet 5
3G_PWR: R2141.2 U2202.6(EN) ; also on sheet 11 31 32
BL_EN: R2254.1 ; also on sheet 11 27 28 29 30
CHG_DET: U2201.9(~{STAT}) ; also on sheet 6
CHG_INT: U2203.5(ALRT_N) ; also on sheet 6
DC_DET: Q2101.3(C) Q2203.3(C) ; also on sheet 6
DDR0_A0: U3000.N3(A0) U3001.N3(A0) ; also on sheet 7 16 17 18 19 20
DDR0_A1: U3000.P7(A1) U3001.P7(A1) ; also on sheet 7 16 17 18 19 20
DDR0_A2: U3000.P3(A2) U3001.P3(A2) ; also on sheet 7 16 17 18 19 20
DDR0_A3: U3000.N2(A3) U3001.N2(A3) ; also on sheet 7 16 17 18 19 20
DDR0_A4: U3000.P8(A4) U3001.P8(A4) ; also on sheet 7 16 17 18 19 20
DDR0_A5: U3000.P2(A5) U3001.P2(A5) ; also on sheet 7 16 17 18 19 20
DDR0_A6: U3000.R8(A6) U3001.R8(A6) ; also on sheet 7 16 17 18 19 20
DDR0_A7: U3000.R2(A7) U3001.R2(A7) ; also on sheet 7 16 17 18 19 20
DDR0_A8: U3000.T8(A8) U3001.T8(A8) ; also on sheet 7 16 17 18 19 20
DDR0_A9: U3000.R3(A9) U3001.R3(A9) ; also on sheet 7 16 17 18 19 20
DDR0_A10: U3000.L7(A10/AP) U3001.L7(A10/AP) ; also on sheet 7 16
DDR0_A11: U3000.R7(A11) U3001.R7(A11) ; also on sheet 7 16
DDR0_A12: U3000.N7(A12/BC#) U3001.N7(A12/BC#) ; also on sheet 7 16
DDR0_A13: U3000.T3(A13) U3001.T3(A13) ; also on sheet 7 16
DDR0_A14: U3000.T7(A14) U3001.T7(A14) ; also on sheet 7 16
DDR0_A15: U3000.M7(A15) U3001.M7(A15) ; also on sheet 7
DDR0_BA0: U3000.M2(BA0) U3001.M2(BA0) ; also on sheet 7 16
DDR0_BA1: U3000.N8(BA1) U3001.N8(BA1) ; also on sheet 7 16
DDR0_BA2: U3000.M3(BA2) U3001.M3(BA2) ; also on sheet 7 16
DDR0_CASN: U3000.K3(CAS#) U3001.K3(CAS#) ; also on sheet 7 16
DDR0_CKE0: U3000.K9(CKE0) U3001.K9(CKE0) ; also on sheet 7 16 17 18 19 20
DDR0_CKE1: U3000.J9(CKE1) U3001.J9(CKE1) ; also on sheet 7 17 18 19 20
DDR0_CLK: R3008.2 U3000.J7(CK) U3001.J7(CK) ; also on sheet 7 16 17 18 19 20
DDR0_CLKN: R3008.1 U3000.K7(CK#) U3001.K7(CK#) ; also on sheet 7 16 17 18 19 20
DDR0_CS0N: U3000.L2(CS#0) U3001.L2(CS#0) ; also on sheet 7 16 17 18 19 20
DDR0_CS1N: U3000.L1(CS#1) U3001.L1(CS#1) ; also on sheet 7 17 18 19 20
DDR0_D0: U3000.E3(DQ0) ; also on sheet 7 16 17 18 19 20
DDR0_D1: U3000.H7(DQ7) ; also on sheet 7 16 17 18 19 20
DDR0_D2: U3000.F7(DQ1) ; also on sheet 7 16 17 18 19 20
DDR0_D3: U3000.H3(DQ4) ; also on sheet 7 16 17 18 19 20
DDR0_D4: U3000.F8(DQ3) ; also on sheet 7 16 17 18 19 20
DDR0_D5: U3000.H8(DQ5) ; also on sheet 7 16 17 18 19 20
DDR0_D6: U3000.G2(DQ6) ; also on sheet 7 16 17 18 19 20
DDR0_D7: U3000.F2(DQ2) ; also on sheet 7 16 17 18 19 20
DDR0_D8: U3001.F8(DQ3) ; also on sheet 7 16 17 18 19 20
DDR0_D9: U3001.G2(DQ6) ; also on sheet 7 16 17 18 19 20
DDR0_D10: U3001.H3(DQ4) ; also on sheet 7 16 17 18 19 20
DDR0_D11: U3001.F7(DQ1) ; also on sheet 7 16 17 18 19 20
DDR0_D12: U3001.F2(DQ2) ; also on sheet 7 16 17 18 19 20
DDR0_D13: U3001.E3(DQ0) ; also on sheet 7 16 17 18 19 20
DDR0_D14: U3001.H7(DQ7) ; also on sheet 7 16 17 18 19 20
DDR0_D15: U3001.H8(DQ5) ; also on sheet 7 16 17 18 19 20
DDR0_D16: U3000.B8(DQ14) ; also on sheet 7 16 17 18 19 20
DDR0_D17: U3000.C3(DQ9) ; also on sheet 7 16 17 18 19 20
DDR0_D18: U3000.D7(DQ8) ; also on sheet 7 16 17 18 19 20
DDR0_D19: U3000.A7(DQ12) ; also on sheet 7 16 17 18 19 20
DDR0_D20: U3000.C8(DQ10) ; also on sheet 7 16 17 18 19 20
DDR0_D21: U3000.C2(DQ11) ; also on sheet 7 16 17 18 19 20
DDR0_D22: U3000.A2(DQ13) ; also on sheet 7 16 17 18 19 20
DDR0_D23: U3000.A3(DQ15) ; also on sheet 7 16 17 18 19 20
DDR0_D24: U3001.C3(DQ9) ; also on sheet 7 16 17 18 19 20
DDR0_D25: U3001.A7(DQ12) ; also on sheet 7 16 17 18 19 20
DDR0_D26: U3001.C2(DQ11) ; also on sheet 7 16 17 18 19 20
DDR0_D27: U3001.C8(DQ10) ; also on sheet 7 16 17 18 19 20
DDR0_D28: U3001.A2(DQ13) ; also on sheet 7 16 17 18 19 20
DDR0_D29: U3001.A3(DQ15) ; also on sheet 7 16 17 18 19 20
DDR0_D30: U3001.D7(DQ8) ; also on sheet 7 16 17 18 19 20
DDR0_D31: U3001.B8(DQ14) ; also on sheet 7 16 17 18 19 20
DDR0_DM0: U3000.E7(LDM) ; also on sheet 7 16 17 18 19 20
DDR0_DM1: U3001.E7(LDM) ; also on sheet 7 16 17 18 19 20
DDR0_DM2: U3000.D3(UDM) ; also on sheet 7 16 17 18 19 20
DDR0_DM3: U3001.D3(UDM) ; also on sheet 7 16 17 18 19 20
DDR0_DQS0M: U3000.G3(LDQS#) ; also on sheet 7 16 17 18 19 20
DDR0_DQS0P: U3000.F3(LDQS) ; also on sheet 7 16 17 18 19 20
DDR0_DQS1M: U3001.G3(LDQS#) ; also on sheet 7 16 17 18 19 20
DDR0_DQS1P: U3001.F3(LDQS) ; also on sheet 7 16 17 18 19 20
DDR0_DQS2M: U3000.B7(UDQS#) ; also on sheet 7 16 17 18 19 20
DDR0_DQS2P: U3000.C7(UDQS) ; also on sheet 7 16 17 18 19 20
DDR0_DQS3M: U3001.B7(UDQS#) ; also on sheet 7 16 17 18 19 20
DDR0_DQS3P: U3001.C7(UDQS) ; also on sheet 7 16 17 18 19 20
DDR0_ODT0: U3000.K1(ODT0) U3001.K1(ODT0) ; also on sheet 7 16 20
DDR0_ODT1: U3000.J1(ODT1) U3001.J1(ODT1) ; also on sheet 7
DDR0_RASN: U3000.J3(RAS#) U3001.J3(RAS#) ; also on sheet 7 16
DDR0_RST: U3000.T2(RESET#) U3001.T2(RESET#) ; also on sheet 7 16
DDR0_WEN: U3000.L3(WE#) U3001.L3(WE#) ; also on sheet 7 16
DDR1_A0: U3002.N3(A0) U3003.N3(A0) ; also on sheet 7 16 17 18 19 20
DDR1_A1: U3002.P7(A1) U3003.P7(A1) ; also on sheet 7 16 17 18 19 20
DDR1_A2: U3002.P3(A2) U3003.P3(A2) ; also on sheet 7 16 17 18 19 20
DDR1_A3: U3002.N2(A3) U3003.N2(A3) ; also on sheet 7 16 17 18 19 20
DDR1_A4: U3002.P8(A4) U3003.P8(A4) ; also on sheet 7 16 17 18 19 20
DDR1_A5: U3002.P2(A5) U3003.P2(A5) ; also on sheet 7 16 17 18 19 20
DDR1_A6: U3002.R8(A6) U3003.R8(A6) ; also on sheet 7 16 17 18 19 20
DDR1_A7: U3002.R2(A7) U3003.R2(A7) ; also on sheet 7 16 17 18 19 20
DDR1_A8: U3002.T8(A8) U3003.T8(A8) ; also on sheet 7 16 17 18 19 20
DDR1_A9: U3002.R3(A9) U3003.R3(A9) ; also on sheet 7 16 17 18 19 20
DDR1_A10: U3002.L7(A10/AP) U3003.L7(A10/AP) ; also on sheet 7 16
DDR1_A11: U3002.R7(A11) U3003.R7(A11) ; also on sheet 7 16
DDR1_A12: U3002.N7(A12/BC#) U3003.N7(A12/BC#) ; also on sheet 7 16
DDR1_A13: U3002.T3(A13) U3003.T3(A13) ; also on sheet 7 16
DDR1_A14: U3002.T7(A14) U3003.T7(A14) ; also on sheet 7 16
DDR1_A15: U3002.M7(A15) U3003.M7(A15) ; also on sheet 7
DDR1_BA0: U3002.M2(BA0) U3003.M2(BA0) ; also on sheet 7 16
DDR1_BA1: U3002.N8(BA1) U3003.N8(BA1) ; also on sheet 7 16
DDR1_BA2: U3002.M3(BA2) U3003.M3(BA2) ; also on sheet 7 16
DDR1_CASN: U3002.K3(CAS#) U3003.K3(CAS#) ; also on sheet 7 16
DDR1_CKE0: U3002.K9(CKE0) U3003.K9(CKE0) ; also on sheet 7 16 17 18 19 20
DDR1_CKE1: U3002.J9(CKE1) U3003.J9(CKE1) ; also on sheet 7 17 18 19 20
DDR1_CLK: R3009.2 U3002.J7(CK) U3003.J7(CK) ; also on sheet 7 16 17 18 19 20
DDR1_CLKN: R3009.1 U3002.K7(CK#) U3003.K7(CK#) ; also on sheet 7 16 17 18 19 20
DDR1_CS0N: U3002.L2(CS#0) U3003.L2(CS#0) ; also on sheet 7 16 17 18 19 20
DDR1_CS1N: U3002.L1(CS#1) U3003.L1(CS#1) ; also on sheet 7 17 18 19 20
DDR1_D0: U3002.E3(DQ0) ; also on sheet 7 16 17 18 19 20
DDR1_D1: U3002.H7(DQ7) ; also on sheet 7 16 17 18 19 20
DDR1_D2: U3002.F7(DQ1) ; also on sheet 7 16 17 18 19 20
DDR1_D3: U3002.G2(DQ6) ; also on sheet 7 16 17 18 19 20
DDR1_D4: U3002.F8(DQ3) ; also on sheet 7 16 17 18 19 20
DDR1_D5: U3002.H8(DQ5) ; also on sheet 7 16 17 18 19 20
DDR1_D6: U3002.H3(DQ4) ; also on sheet 7 16 17 18 19 20
DDR1_D7: U3002.F2(DQ2) ; also on sheet 7 16 17 18 19 20
DDR1_D8: U3003.F8(DQ3) ; also on sheet 7 16 17 18 19 20
DDR1_D9: U3003.G2(DQ6) ; also on sheet 7 16 17 18 19 20
DDR1_D10: U3003.H3(DQ4) ; also on sheet 7 16 17 18 19 20
DDR1_D11: U3003.F7(DQ1) ; also on sheet 7 16 17 18 19 20
DDR1_D12: U3003.F2(DQ2) ; also on sheet 7 16 17 18 19 20
DDR1_D13: U3003.E3(DQ0) ; also on sheet 7 16 17 18 19 20
DDR1_D14: U3003.H7(DQ7) ; also on sheet 7 16 17 18 19 20
DDR1_D15: U3003.H8(DQ5) ; also on sheet 7 16 17 18 19 20
DDR1_D16: U3002.B8(DQ14) ; also on sheet 7 16 17 18 19 20
DDR1_D17: U3002.C3(DQ9) ; also on sheet 7 16 17 18 19 20
DDR1_D18: U3002.D7(DQ8) ; also on sheet 7 16 17 18 19 20
DDR1_D19: U3002.A7(DQ12) ; also on sheet 7 16 17 18 19 20
DDR1_D20: U3002.C8(DQ10) ; also on sheet 7 16 17 18 19 20
DDR1_D21: U3002.C2(DQ11) ; also on sheet 7 16 17 18 19 20
DDR1_D22: U3002.A2(DQ13) ; also on sheet 7 16 17 18 19 20
DDR1_D23: U3002.A3(DQ15) ; also on sheet 7 16 17 18 19 20
DDR1_D24: U3003.C3(DQ9) ; also on sheet 7 16 17 18 19 20
DDR1_D25: U3003.A7(DQ12) ; also on sheet 7 16 17 18 19 20
DDR1_D26: U3003.C2(DQ11) ; also on sheet 7 16 17 18 19 20
DDR1_D27: U3003.C8(DQ10) ; also on sheet 7 16 17 18 19 20
DDR1_D28: U3003.A2(DQ13) ; also on sheet 7 16 17 18 19 20
DDR1_D29: U3003.A3(DQ15) ; also on sheet 7 16 17 18 19 20
DDR1_D30: U3003.D7(DQ8) ; also on sheet 7 16 17 18 19 20
DDR1_D31: U3003.B8(DQ14) ; also on sheet 7 16 17 18 19 20
DDR1_DM0: U3002.E7(LDM) ; also on sheet 7 16 17 18 19 20
DDR1_DM1: U3003.E7(LDM) ; also on sheet 7 16 17 18 19 20
DDR1_DM2: U3002.D3(UDM) ; also on sheet 7 16 17 18 19 20
DDR1_DM3: U3003.D3(UDM) ; also on sheet 7 16 17 18 19 20
DDR1_DQS0M: U3002.G3(LDQS#) ; also on sheet 7 16 17 18 19 20
DDR1_DQS0P: U3002.F3(LDQS) ; also on sheet 7 16 17 18 19 20
DDR1_DQS1M: U3003.G3(LDQS#) ; also on sheet 7 16 17 18 19 20
DDR1_DQS1P: U3003.F3(LDQS) ; also on sheet 7 16 17 18 19 20
DDR1_DQS2M: U3002.B7(UDQS#) ; also on sheet 7 16 17 18 19 20
DDR1_DQS2P: U3002.C7(UDQS) ; also on sheet 7 16 17 18 19 20
DDR1_DQS3M: U3003.B7(UDQS#) ; also on sheet 7 16 17 18 19 20
DDR1_DQS3P: U3003.C7(UDQS) ; also on sheet 7 16 17 18 19 20
DDR1_ODT0: U3002.K1(ODT0) U3003.K1(ODT0) ; also on sheet 7 16 20
DDR1_ODT1: U3002.J1(ODT1) U3003.J1(ODT1) ; also on sheet 7
DDR1_RASN: U3002.J3(RAS#) U3003.J3(RAS#) ; also on sheet 7 16
DDR1_RST: U3002.T2(RESET#) U3003.T2(RESET#) ; also on sheet 7 16
DDR1_WEN: U3002.L3(WE#) U3003.L3(WE#) ; also on sheet 7 16
DDRIO_PWROFF: R3010.2 ; also on sheet 6 16 17 18 19 20
I2C0_SCL_PMIC: R2134.1 R2255.1 U2101.A3(SCL) U2102.A3(SCL) U2103.E7(SCL) U2203.7(SCL) U2204.24(SCL) U2205.A3(SCL) U2206.A3(SCL) U2209.6(SCL) ; also on sheet 6
I2C0_SDA_PMIC: R2133.1 R2253.1 U2101.B1(SDA) U2102.B1(SDA) U2103.E6(SDA) U2203.8(SDA) U2204.23(SDA) U2205.B1(SDA) U2206.B1(SDA) U2209.5(SDA) ; also on sheet 6
LCD_EN: R2252.1 ; also on sheet 11 29
NTC: BAT2100.3(TS) P2103.1 R2118.1 R2119.2 U2103.D5(THERMBAT)
NTC (page 22.Power-ACT8846_2CELL (option)): BAT2200.3(TS) P2203.1 R2225.1 R2230.2 R2231.2 U2201.10(TS)
OTG_VBUS_DRV: U2105.4(EN) U2210.4(EN) ; also on sheet 6
PLAY_ON: ED2200.1 R2258.2 R2264.2 R2266.1 SW2200.1
PMIC_INT: U2103.J2(INTB) U2209.3(~{INT}) ; also on sheet 6
PMIC_PWROFF: C2160.2 ED2100.1 R2132.2 SW2100.1 SW2100.2 U2103.F2(GPIO4)
PMIC_PWRON: C2158.1 ED2101.1 R2135.1 SW2101.1 SW2101.2 T2100.1 U2103.E4(PWRON)
PMIC_PWRON (page 22.Power-ACT8846_2CELL (option)): R2263.2 U2204.31(nPBIN)
PMIC_RSTO: R2244.2 U2204.33(nRTSO)
PMIC_SLEEP: U2101.A1(VSEL) U2102.A1(VSEL) U2103.F4(SLEEP) U2205.A1(VSEL) U2206.A1(VSEL) ; also on sheet 6
PMIC_VSEL: R2247.2 U2204.8(VSELR2) U2204.44(GPIO2/VSELR4) U2204.45(GPIO1/VSELR3) ; also on sheet 11
PWR_EN: D2202.2(K) D2203.3(K) R2260.1 U2200.6(EN) U2204.16(PWREN) U2204.32(PWRHLD)
PWR_HOLD: D2203.2(A2) ; also on sheet 6
PWR_KEY: U2204.9(nPBSTAT) ; also on sheet 6
RESET: R2130.2 R2242.2 R2244.1 U2103.F5(RESETO) U2207.2(/Reset) ; also on sheet 6
RTC_CLKOUT: R2139.2 U2103.E5(RTCOUT/GPIO1)
RTC_CLKOUT1: C2157.2 R2126.1 R2257.1 R2265.1 U2209.7(CLKOUT) ; also on sheet 6
RTC_CLKOUT2: C2169.2 C2272.2 R2139.1 R2140.1 R2257.2 R2259.2 ; also on sheet 44 47 48
SDMMC_PWR: R2249.1 R2267.2 ; also on sheet 11
VADP: C2127.1 Q2100.3(DRAIN) R2111.2 R2113.1 U2103.A1(VADP2) U2103.B1(VADP1) U2103.D1(VADPA)
VREF: C2215.2 R2214.2 R2215.2 R2225.2 U2201.12(VREF)
VREFAO_DDR0: C3026.2 C3027.1 C3028.1 U3000.H1(VREFDQ) U3000.M8(VREFCA) U3001.H1(VREFDQ) U3001.M8(VREFCA) ; also on sheet 7 16 17 18 19 20
VREFAO_DDR1: C3029.1 C3030.2 C3031.1 U3002.H1(VREFDQ) U3002.M8(VREFCA) U3003.H1(VREFDQ) U3003.M8(VREFCA) ; also on sheet 7 16 17 18 19 20
WIFI_PWR: R2250.1 ; also on sheet 11
N61796183: R3002.1 U3000.L8(ZQ0)
N61796414: R3004.1 U3001.L9(ZQ1)
N61796421: R3006.1 U3000.L9(ZQ1)
N61796439: R3003.1 U3002.L8(ZQ0)
N61796518: R3001.1 U3003.L8(ZQ0)
N61796656: R3007.1 U3002.L9(ZQ1)
N61796665: R3005.1 U3003.L9(ZQ1)
N61796777: R3000.1 U3001.L8(ZQ0)
N62668237: C3032.2 Q3000.1(GATE) R3010.1
N62825342: Q2101.1(B) R2103.1 R2105.2
N62825457: C2102.2 R2102.2
N62825981: C2153.1 Q2102.1(GATE) R2124.1 R2128.2
N62826017: C2152.2 L2108.1 Q2102.3(DRAIN) U2104.4(EN) U2104.5(VIN) U2104.6(NC)
N62826021: D2101.1(A) L2108.2 U2104.1(LX)
N62826029: C2154.1 R2125.2 R2129.1 U2104.3(FB)
N62826209: Q2103.1(B) R2131.2
N62826213: Q2103.3(C) R2128.1
N62920579: C2200.1 L2200.1 U2200.3(SW)
N62920583: C2206.1 R2204.2 R2206.2 R2211.1
N62920589: R2206.1 U2200.8(FB)
N62920605: C2209.2 R2205.2 U2200.7(VCC)
N62920624: C2200.2 R2201.1
N62920626: R2201.2 U2200.5(BST)
N62920630: R2205.1 R2210.1 U2200.1(AAM)
N62922485: R2235.2 R2237.2 U2204.29(OUT1)
N62922615: L2207.1 U2204.1(SW3) U2204.2(SW3)
N62922840: C2261.2 U2204.37(OUT13)
N62922876: C2270.1 U2204.17(REFBP)
N62922966: L2206.2 U2204.26(SW4)
N62923025: L2204.2 U2204.28(SW1)
N62923038: L2203.1 U2204.11(SW2) U2204.12(SW2)
N62925070: C2201.1 Q2200.1(GATE) Q2201.1(GATE) R2203.1 R2208.2
N62925110: C2202.2 C2203.2 Q2201.3(DRAIN) R2200.1 U2201.6(ACP)
N62925175: C2214.2 C2217.2 L2201.2 R2212.1 U2201.16(SRP)
N62925234: C2212.2 L2201.1 U2201.1(SW) U2201.24(SW)
N62925236: R2214.1 R2219.2 U2201.17(ACSET)
N62925283: R2213.1 R2218.2 U2201.18(OVPSET)
N62925285: Q2202.1(GATE) R2207.2 R2216.2
N62925385: C2221.2 R2222.1 U2201.4(AVCC)
N62925396: R2216.1 U2201.19(~{BATDRV})
N62925499: R2208.1 U2201.8(ACDRV)
N62925601: C2222.2 U2201.11(TTC)
N62925678: C2212.1 U2201.21(BTST)
N62925686: C2216.2 U2201.20(REGN)
N62925690: R2215.1 R2220.2 U2201.13(ISET1)
N62926691: Q2203.1(B) R2217.1 R2221.2
N62927339: D2202.1(A) R2256.1
N62927358: D2203.1(A1) R2258.1
N62928400: R2261.1 R2262.2 U2210.3(OCB)
N62938688: Q2210.3(C) R2263.1
N62938714: Q2210.1(B) R2264.1
N63004012: L2208.1 U2206.D3(SW) U2206.D4(SW) U2206.E3(SW) U2206.E4(SW)
N63004039: C2249.1 R2239.2 U2206.A2(EN)
N63004256: L2205.1 U2205.D3(SW) U2205.D4(SW) U2205.E3(SW) U2205.E4(SW)
N63006796: C2248.1 R2238.2 U2205.A2(EN)
N63010918: C2262.1 Q2206.1(GATE) R2245.1 R2248.2
N63010969: Q2208.3(C) R2248.1
N63010987: Q2208.1(B) R2252.2
N63013069: C2271.2 Q2205.1(GATE) R2250.2
N63013844: C2266.1 Q2204.1(GATE) R2249.2
N63064311: C2265.1 Q2207.1(GATE) R2246.1 R2251.2
N63064366: Q2209.3(C) R2251.1
N63064382: Q2209.1(B) R2254.2
N63258176: C2273.1 U2209.1(OSCI) Y2200.1
N63258197: U2209.2(OSCO) Y2200.2
N63260962: C2229.1 R2232.1 R2236.2 U2203.2(CELL)
N63261023: C2230.1 R2233.1 U2203.3(VDD)
N63262094: C2219.1 L2202.1 U2202.3(SW)
N63262129: R2227.1 U2202.8(FB)
N63262131: C2220.1 R2224.2 R2227.2 R2229.1
N63262145: C2226.2 R2226.2 U2202.7(VCC)
N63262178: R2226.1 R2228.1 U2202.1(AAM)
N63262182: R2223.2 U2202.5(BST)
N63262184: C2219.2 R2223.1
N63630377: R2115.1 R2116.2 U2103.G2(VFB5)
N63630731: R2126.2 U2103.G7(C32KOUT)
N63630741: U2103.J6(DM) U2103.K6(DP)
N63630758: L2104.1 U2103.F8(LX3)
N63630810: L2106.1 U2103.J1(LX5) U2103.K1(NC)
N63630814: R2127.1 U2103.D6(CharerLED/GPIO0)
N63630859: C2141.1 R2119.1 U2103.D2(VCHGREGA)
N63630939: C2149.1 U2103.J8(XIN) Y2100.1
N63631045: C2147.1 U2103.H7(VREF)
N63631062: C2132.2 L2107.1 R2117.2 U2103.C4(ILP)
N63631238: C2146.2 C2148.2 R2121.1 U2103.D3(ICM)
N63631280: C2151.1 U2103.H8(XOUT) Y2100.2
N63631334: C2150.1 U2103.B4(VCHGREGD)
N63631378: L2107.2 U2103.A2(CHG_LX2) U2103.A3(CHG_LX1)
N63632009: L2100.1 U2103.A8(LX1)
N63632015: L2101.1 U2103.C8(LX2)
N63632144: L2103.1 U2103.F1(LX4)
N63635400: C2100.1 Q2100.1(GATE) R2100.2 R2104.1
N63635402: R2104.2 U2100.1(VOUT)
N63635457: R2101.2 R2106.1 U2100.3(VDD)
N63636934: L2105.1 U2101.D3(SW) U2101.D4(SW) U2101.E3(SW) U2101.E4(SW)
N63637068: R2112.1 U2101.A2(EN)
N63637150: L2102.1 U2102.D3(SW) U2102.D4(SW) U2102.E3(SW) U2102.E4(SW)
N63637171: R2110.1 U2102.A2(EN)
N63639795: R2122.1 R2123.2 U2105.3(OCB)
N63646505: C2166.1 Q2104.1(GATE) R2136.1 R2137.1
N63646700: Q2105.1(B) R2141.1
N63646707: Q2105.3(C) R2137.2
N64035192: R2209.1 U2201.7(CMSRC)

Not connected (* = marked no-connect by the designer): U2201 14(CELL)*; U2204 34(nIRQ)* 35(GPIO6)* 36(GPIO5)* 39(GPIO4)* 43(GPIO3)*

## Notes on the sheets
sheet 13
- DC IN
- SYSTEM POWER
- Note:
  Please use a 5V DC.
- PMU
  Channel
- TIMER
  (2mS)
- OutPut
  voltage
- PowerName
- VCC_IO
- DCDC1
- solt:8
- 3.3V
- VCC_20
- DCDC2
- solt:0
- 2.0V
- VCCIO_LCD
- VCC_LOG
- DCDC3
- DCDC4
- OFF
- solt:5
- 1.0V
- 3.3V
- VCC_DDR
- DCDC5
- solt:4
- 1.2V
- VDD_ARM
- ExDCDC1
- solt:2
- 1.0V
- VDD_GPU
- ExDCDC2
- solt:3
- 1.0V
- VCCA_TP
- VOUT3
- OFF
- 3.3V
- VCCIO_WL
- VCC_SD
- VOUT4
- VOUT5
- OFF
- solt:9
- 1.8V
- 3.0V
- VDD10_LCD
- VOUT7
- OFF
- 1.0V
- VCCIO_SD
- VOUT8
- solt:9
- 3.0V
- VCC18_LCD
- VOUT6
- OFF
- 1.8V
- VDD_10
- VOUT9
- solt:1
- 1.0V
- VCC_18
- VOUT10
- solt:6
- 1.8V
- VCCA_CODEC
- VCC_PMUIO
- VOUT1
- VOUT2
- OFF
- solt:7
- 3.3V
- 3.3V
- RESET
- solt:15+32mS
- VDD_CPU、VDD_GPU
- Boost
- OTG POWER Switch
- R2414 Close to R2413
- 3G POWER
- BATTERY
- POWER KEY
sheet 14
- DC IN
- CHARGE and Power Path
- Note:
  Please use a 12V DC.
- PowerName
- PMU
  Channel
- TIMER
  (1mS)
- OutPut
  voltage
- SYSTEM POWER
- BATTERY
- VCC_IO
- DCDC2
- solt:6
- 3.3V
- VCC_20
- DCDC4
- solt:0
- 2.0V
- Note:The ACT8846-2cell Solution only for 9.7'' eDP Panel.
- VCCIO_LCD
- ExMos
- OFF
- 3.3V
- VCC_LOG
- DCDC3
- solt:3
- 1.0V
- VCC_DDR
- DCDC1
- solt:2
- 1.2V
- VDD_ARM
- VDD_GPU
- ExDCDC1
- ExDCDC2
- solt:2A
- solt:2B
- 1.0V
- 1.0V
- VCCA_TP
- OUT8
- OFF
- 3.3V
- VCC_SD
- ExMos
- solt:6A
- 3.3V
- VCCIO_WL
- ExMos
- OFF
- 1.8V
- VDD10_LCD
- OUT6
- OFF
- 1.0V
- VCCIO_SD
- OUT5
- solt:6
- 3.3V
- VCC18_LCD
- VDD_10
- OUT10
- OUT12
- OFF
- solt:1
- 1.0V
- 1.8V
- VCC_18
- OUT11
- solt:4
- 1.8V
- VCC_PMUIO
- OUT9
- solt:5
- 3.3V
- VCCA_CODEC
- OUT7
- OFF
- 3.3V
- RESET
- solt:6+40mS
- SYR827
- I2C Address: 0x40h
- SYR828
- I2C Address: 0x41h
- RTC
- SLAVE ADDRESS
  READ  D1
  WRITE D0
- RTC POWER
sheet 15
- DDR3 Channel-0
- DDR3 Channel-1
- DDR0 FILTER
- DDR1 FILTER
